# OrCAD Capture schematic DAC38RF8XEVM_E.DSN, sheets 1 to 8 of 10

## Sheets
1 SHEET 02 - DAC: size B; title: DAC; rev: E; note: DAC38RF8xEVM
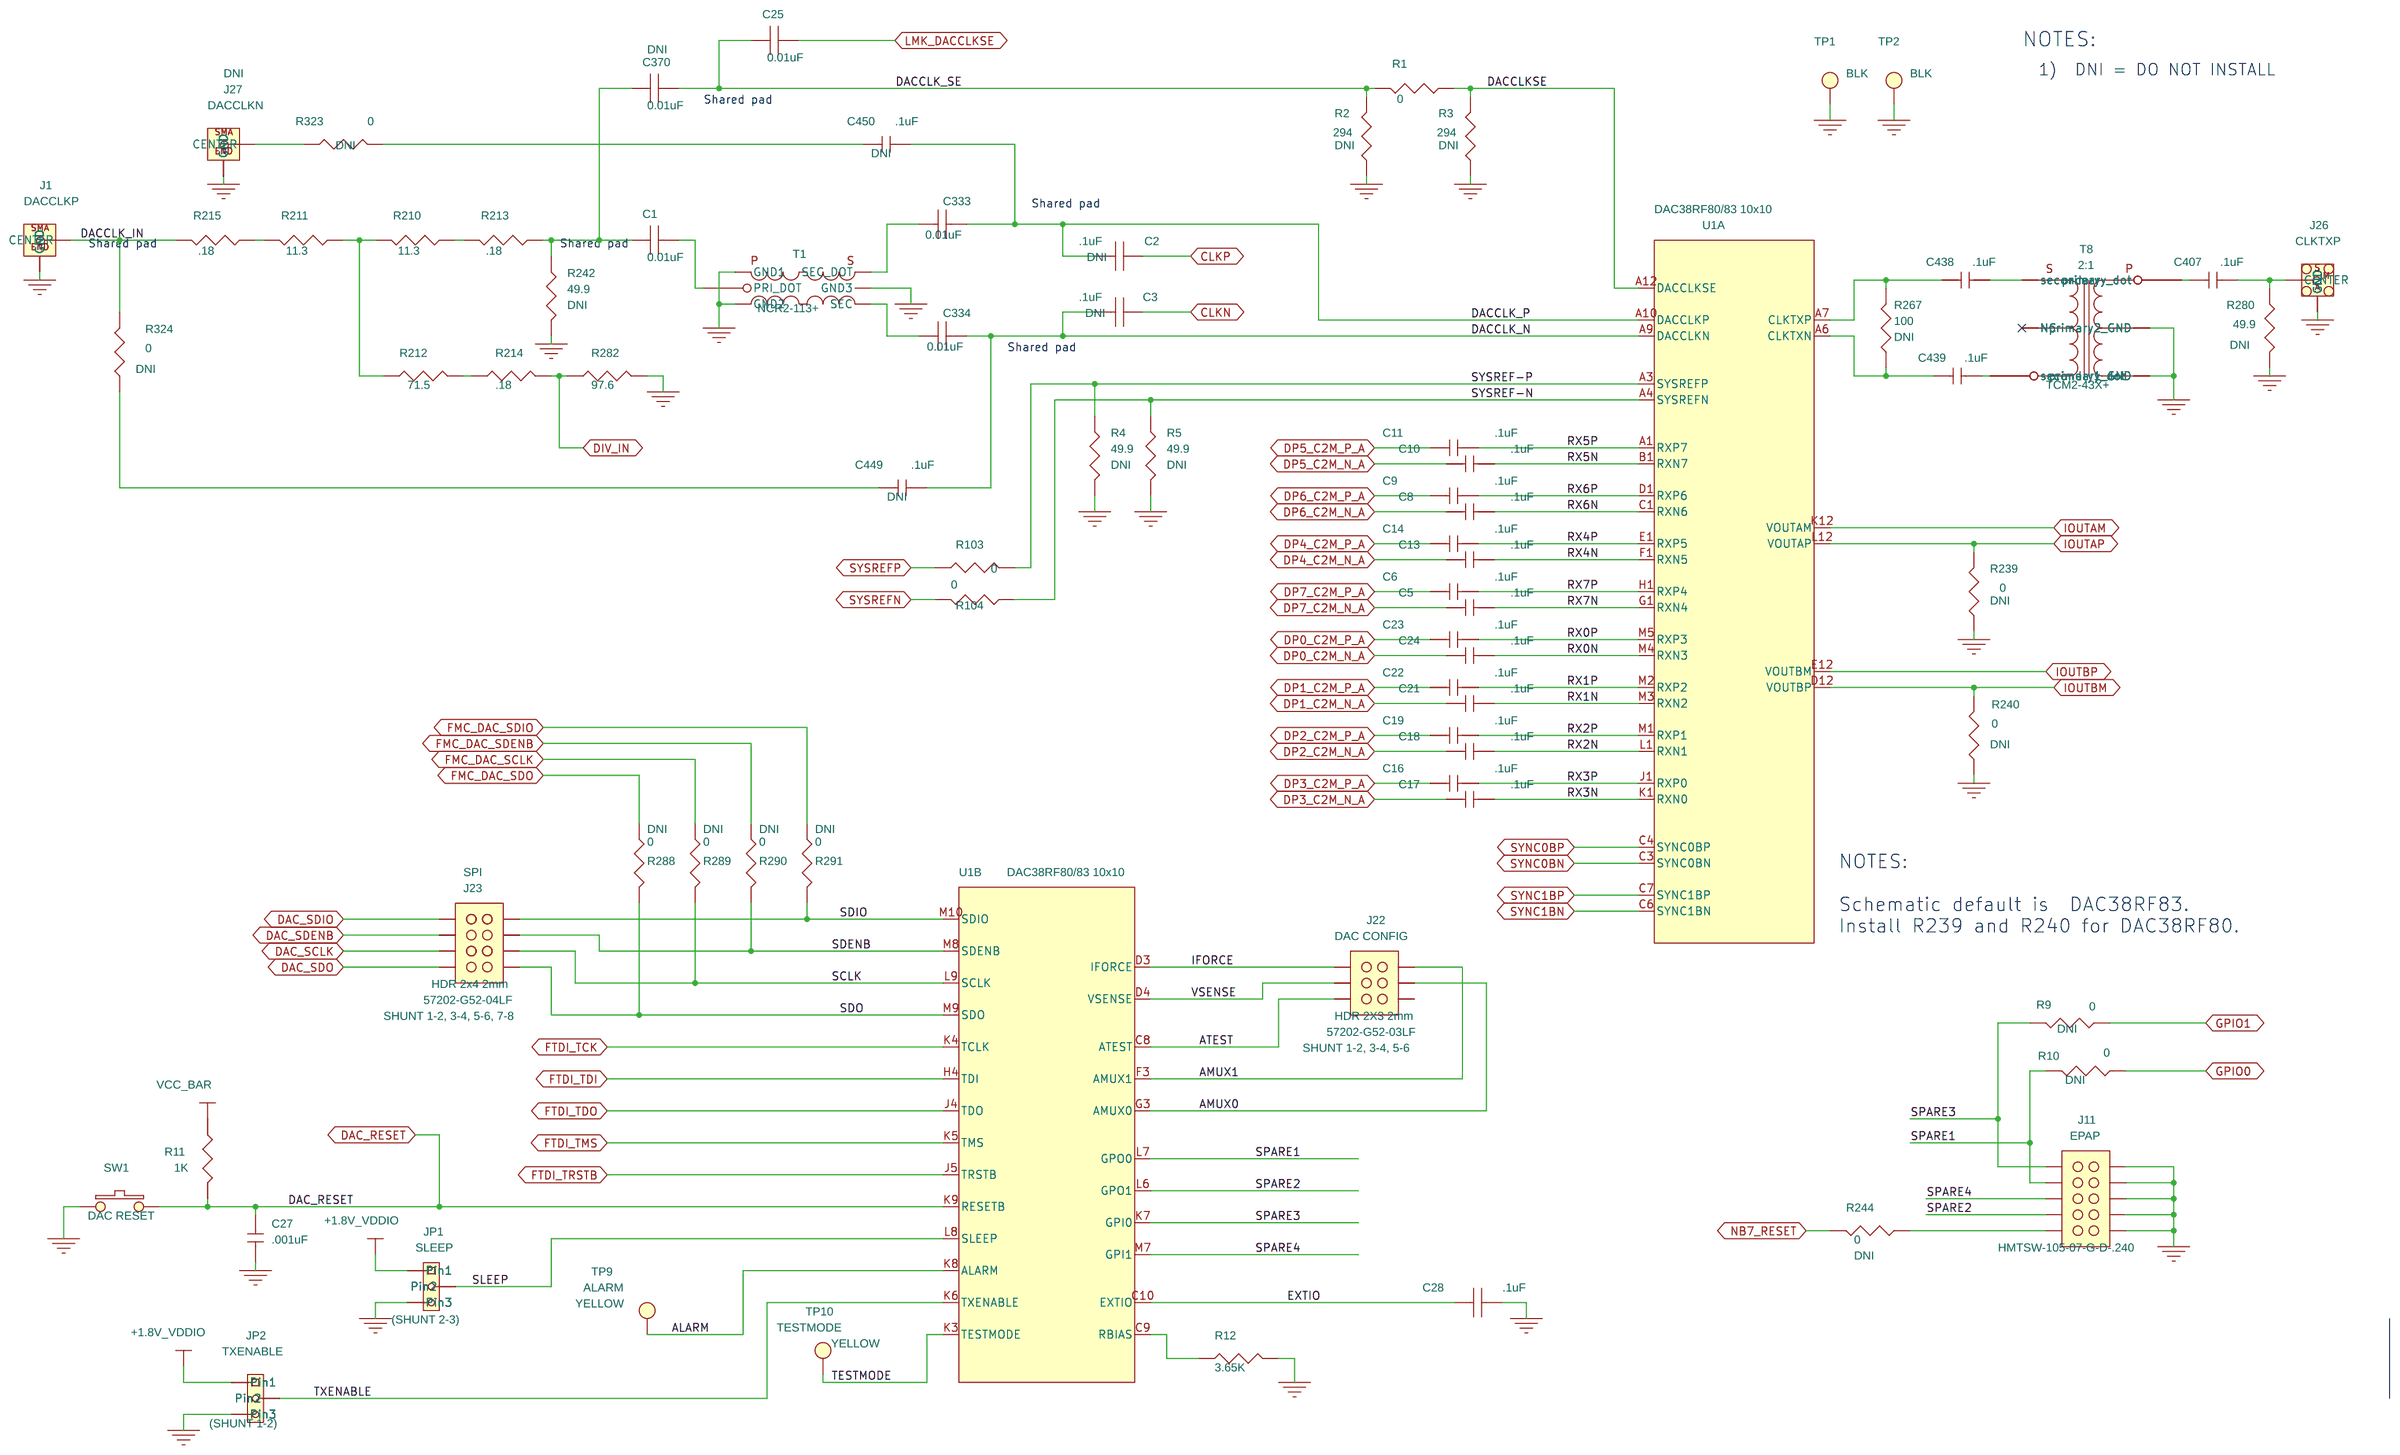
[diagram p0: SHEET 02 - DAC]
2 SHEET 03 - DAC POWER: size B; title: DAC POWER
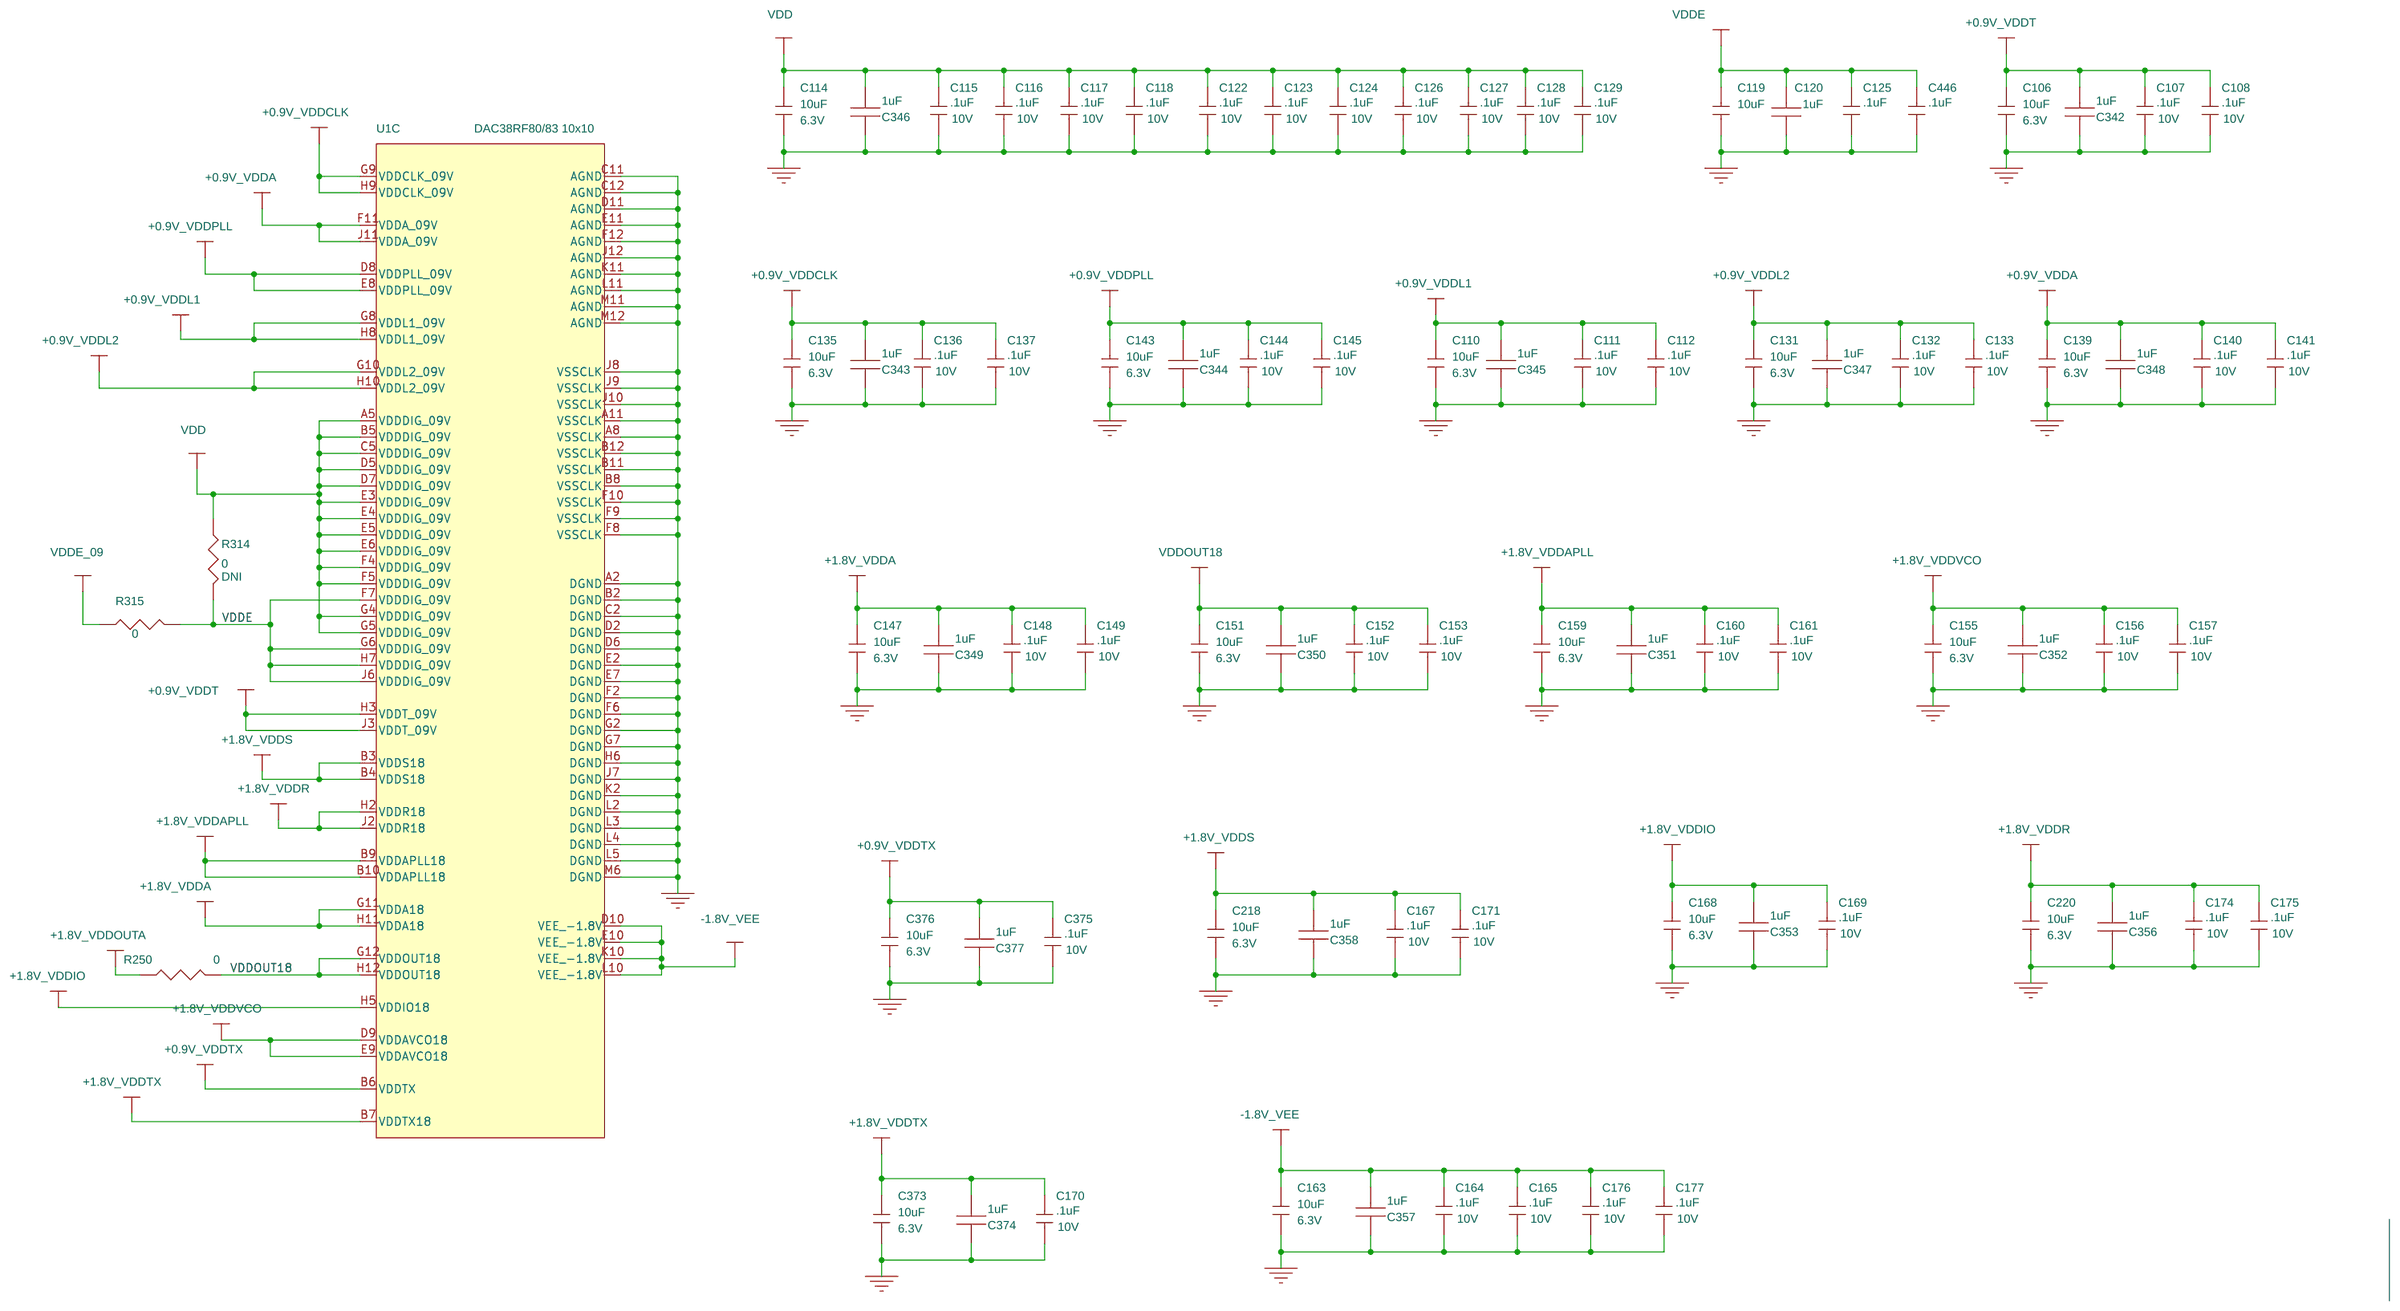
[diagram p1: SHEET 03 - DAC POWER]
3 SHEET 04 - DAC OUTPUTS: size B; title: DAC OUTPUT
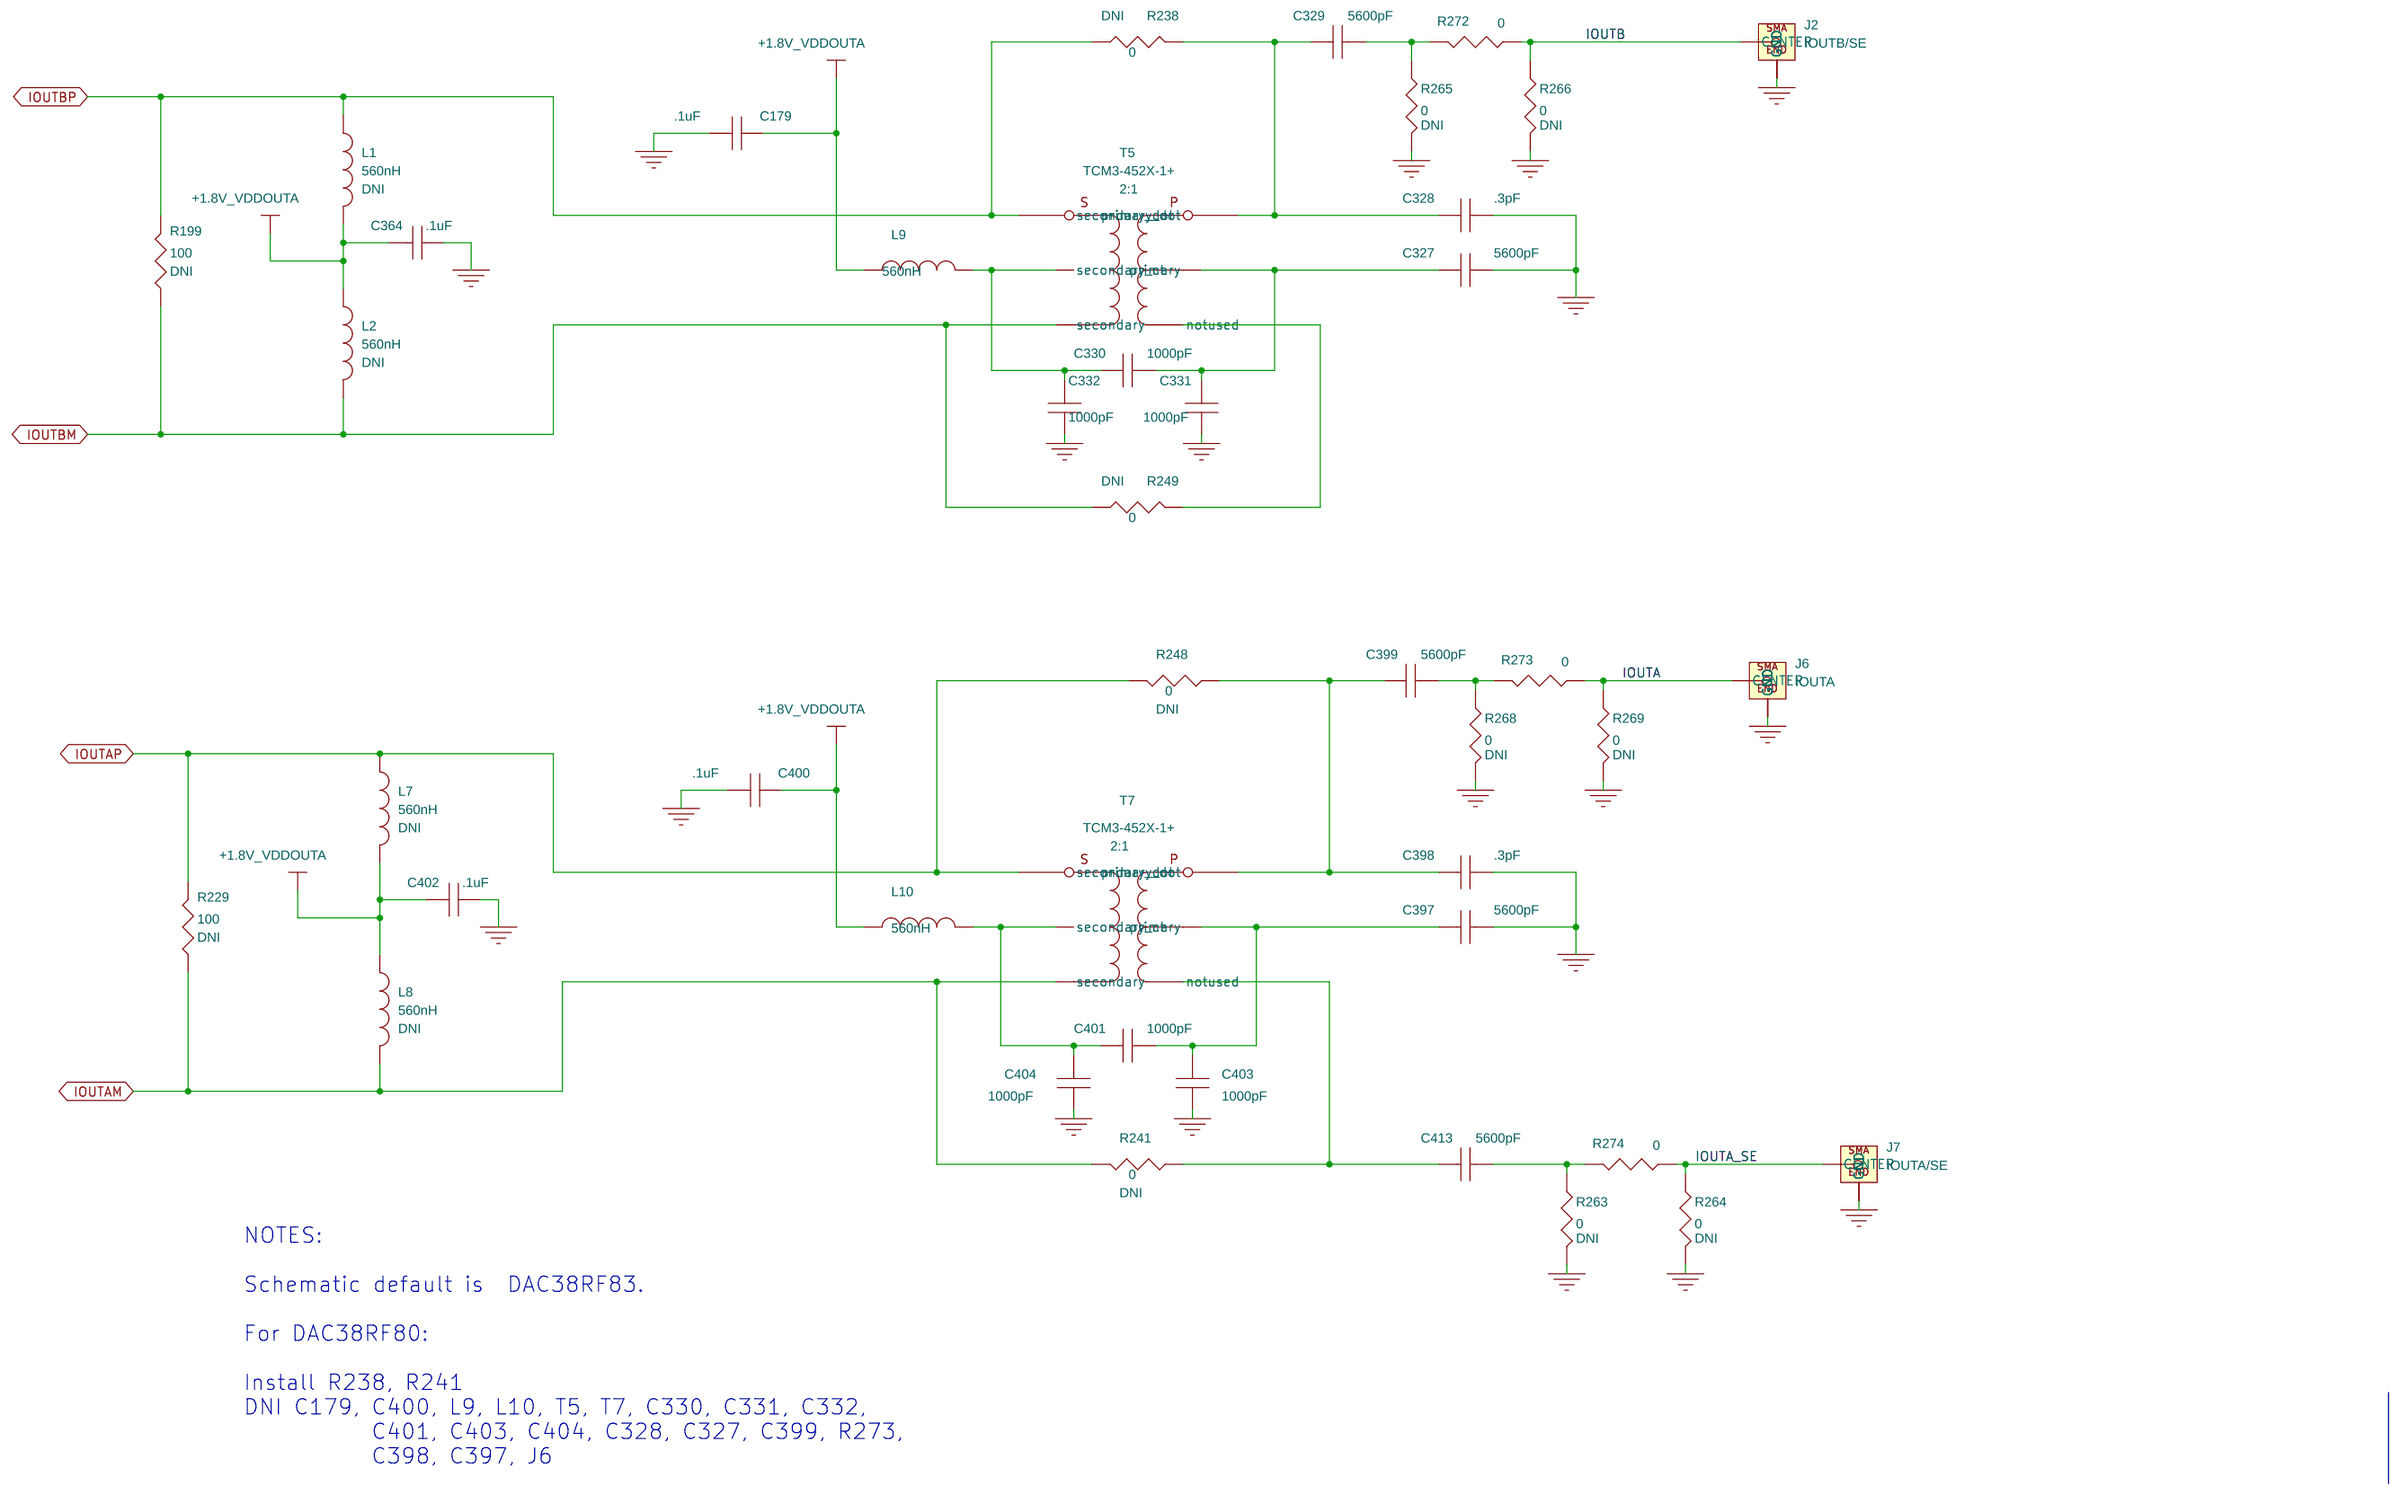
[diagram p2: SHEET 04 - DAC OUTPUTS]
4 SHEET 05 - LMK INPUTS & OUTPUTS: size B; title: LMK
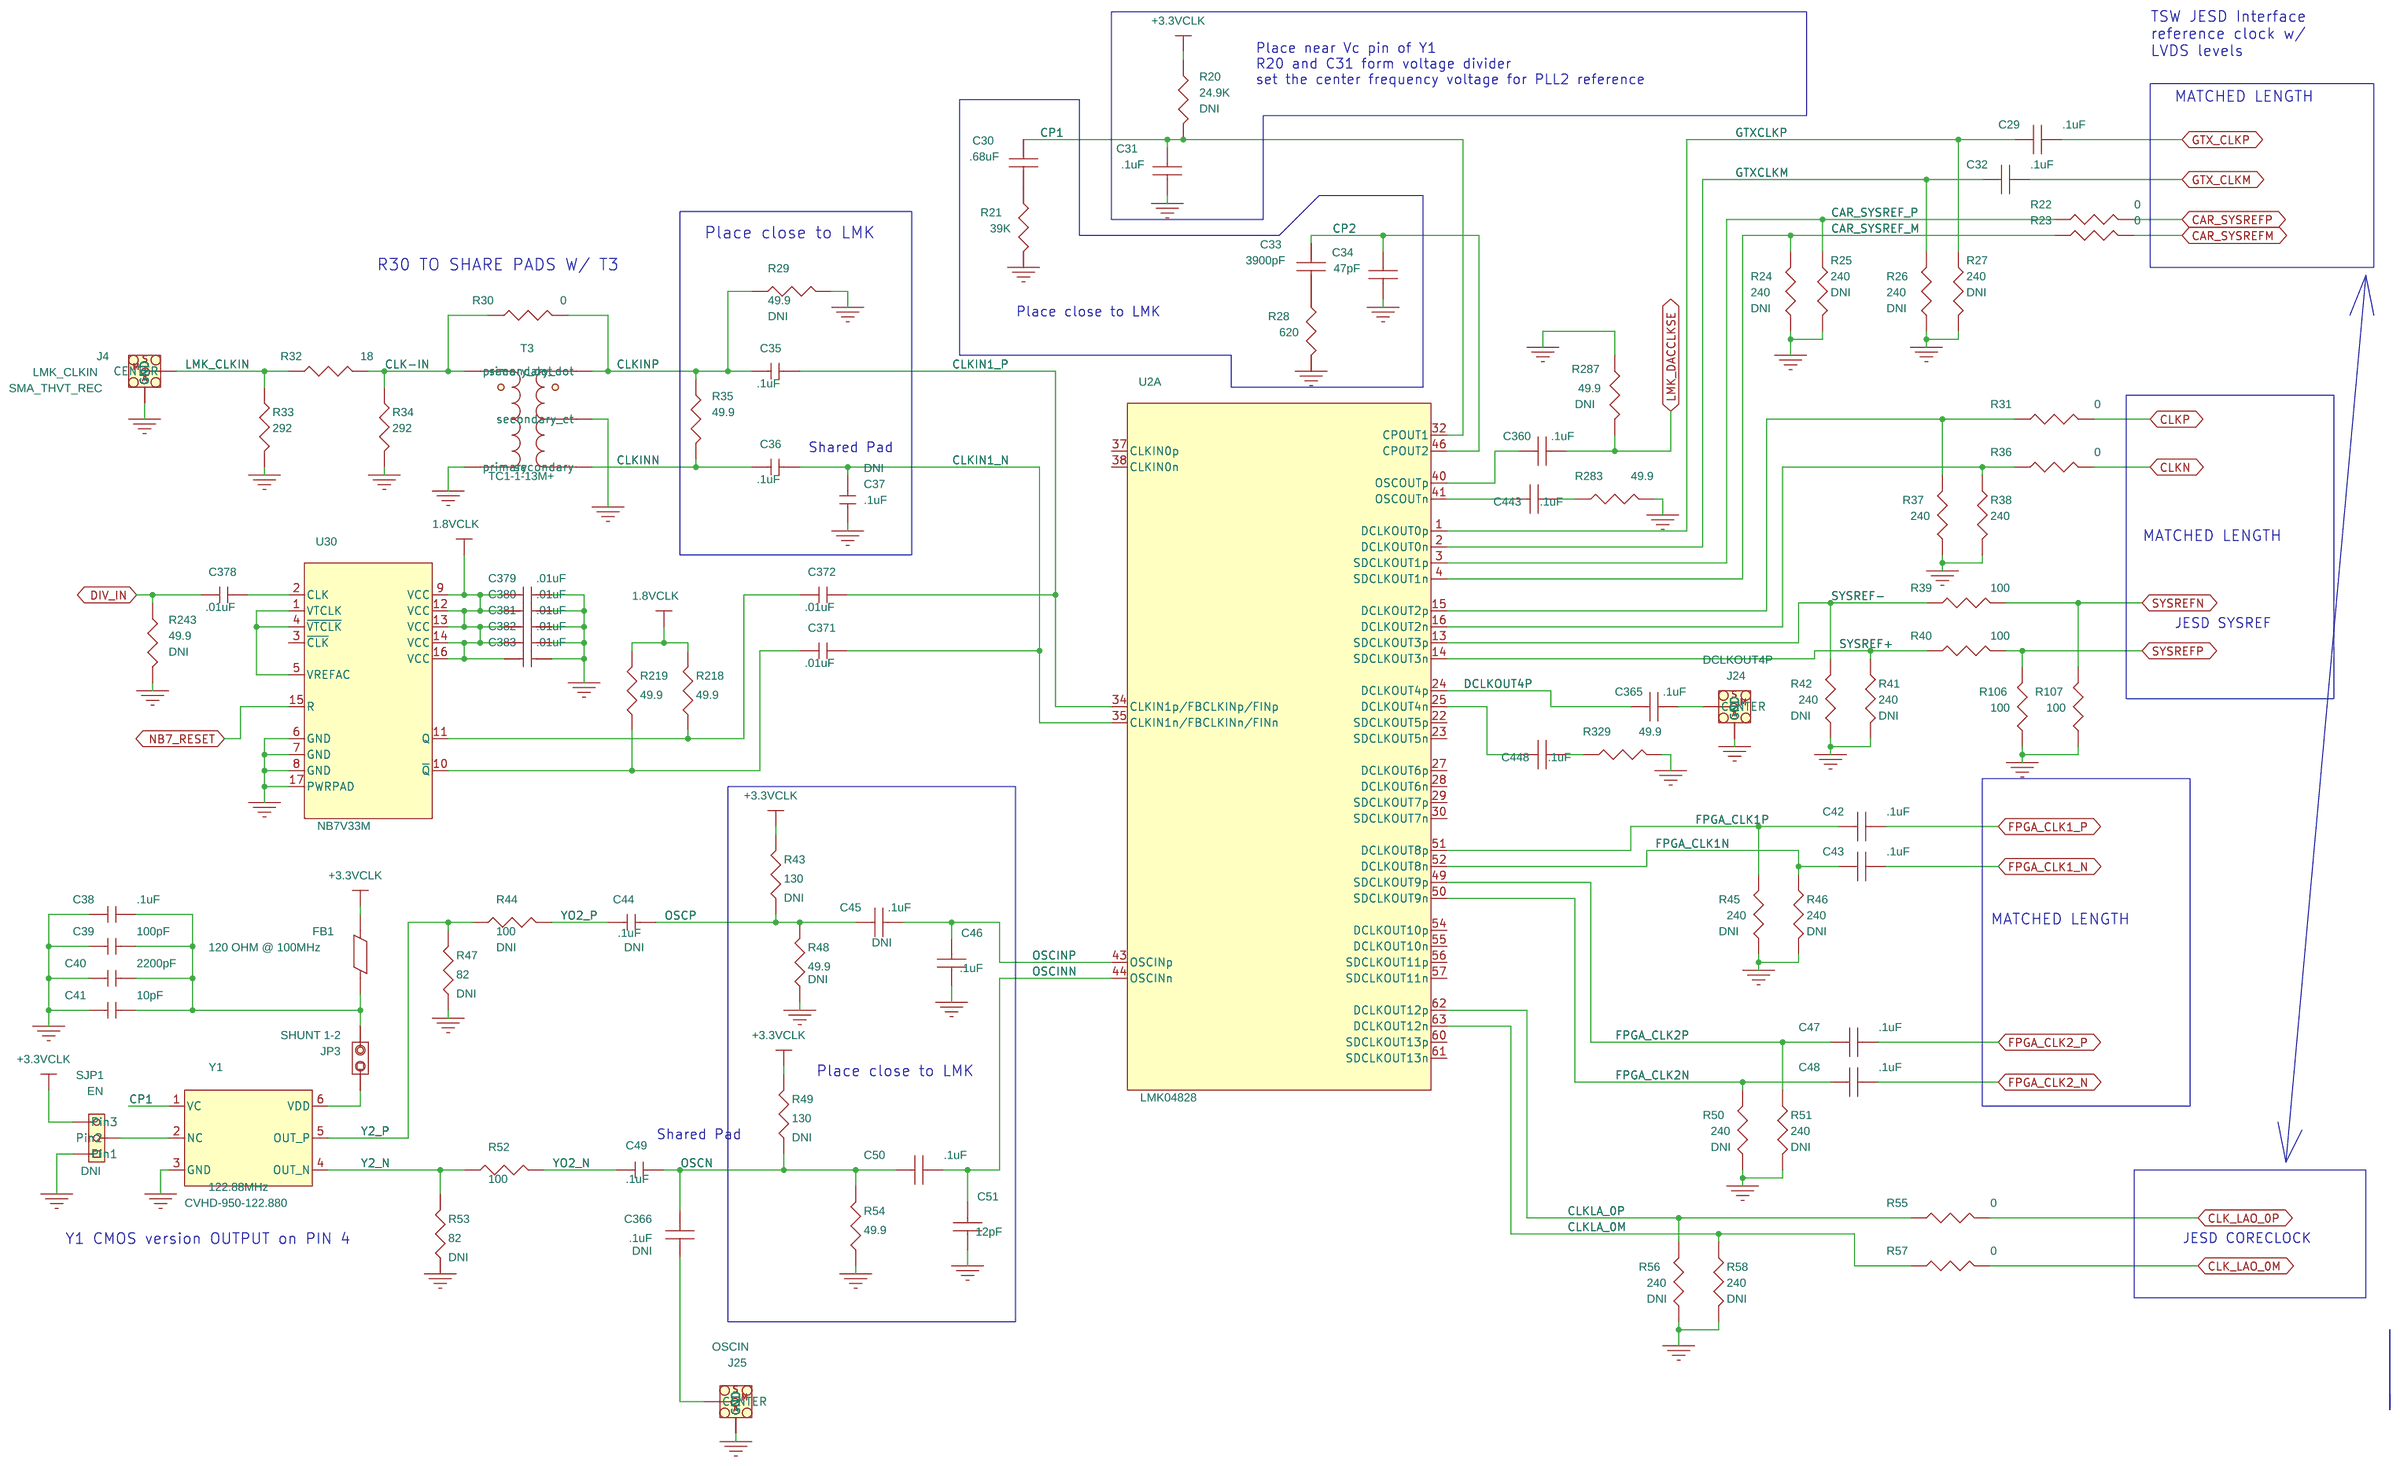
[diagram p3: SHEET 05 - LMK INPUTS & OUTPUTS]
5 SHEET 06 - LMK POWER & CONF: size B; title: LMK
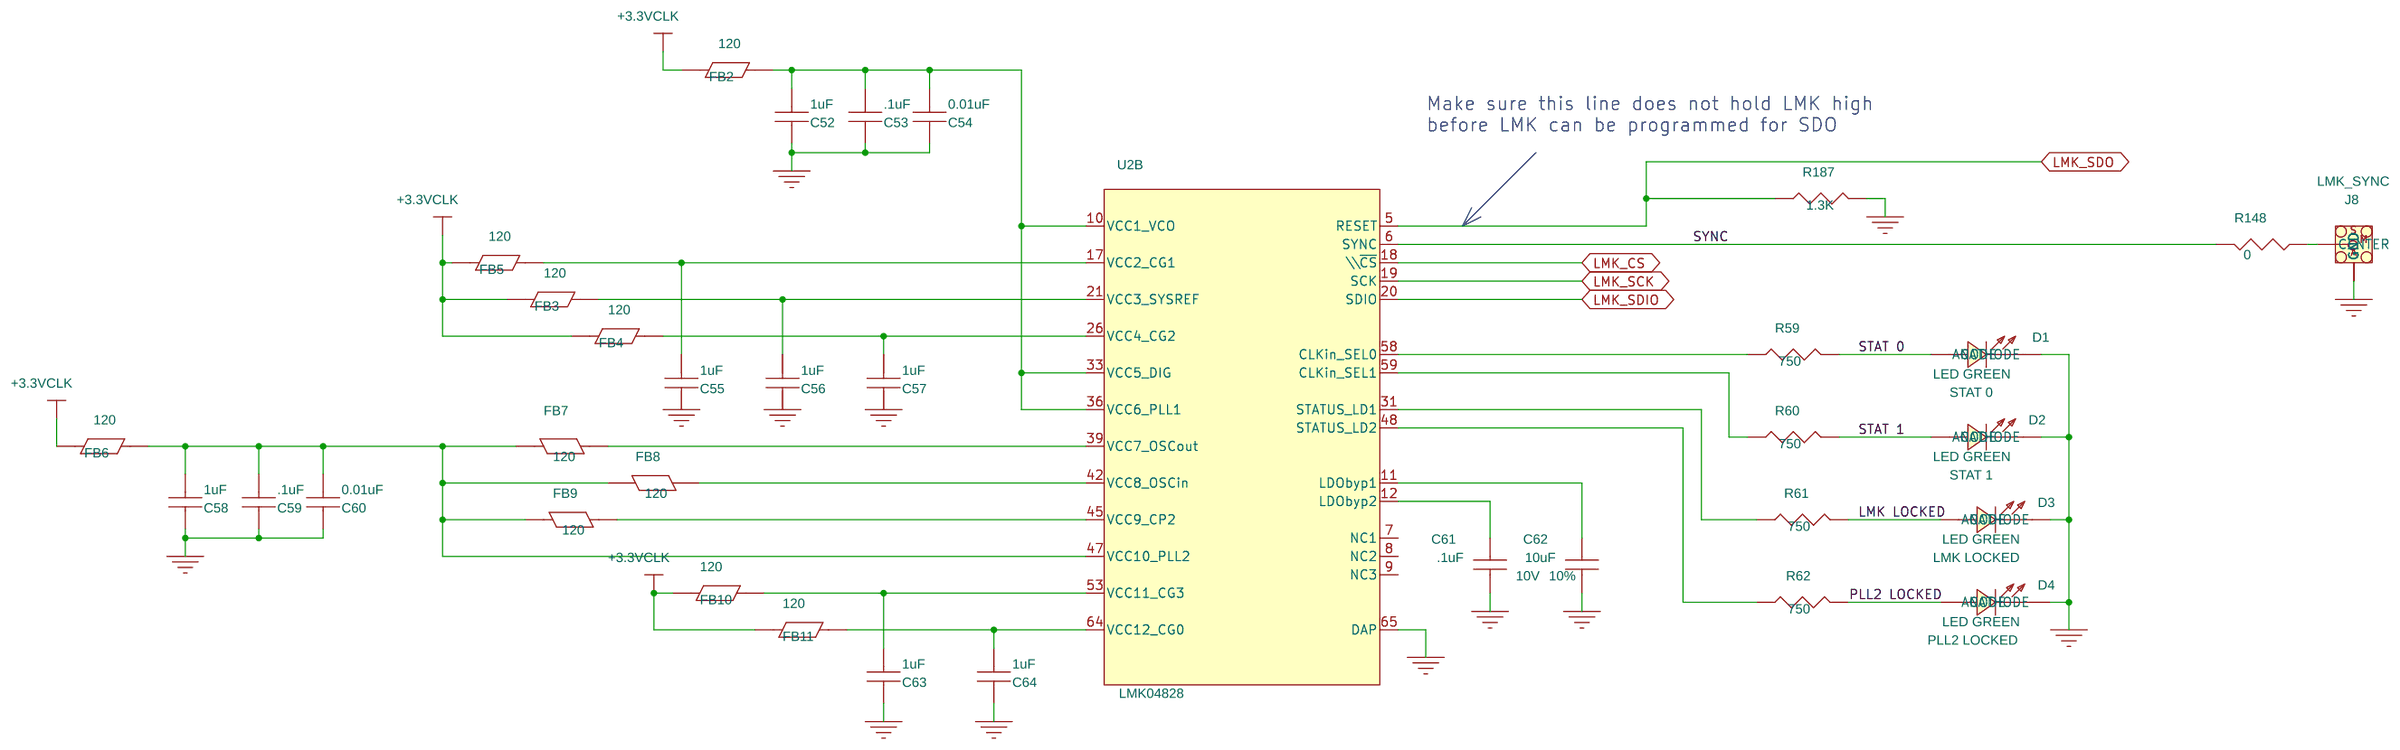
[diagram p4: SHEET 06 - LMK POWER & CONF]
6 SHEET 01 - COVER: title: COVER
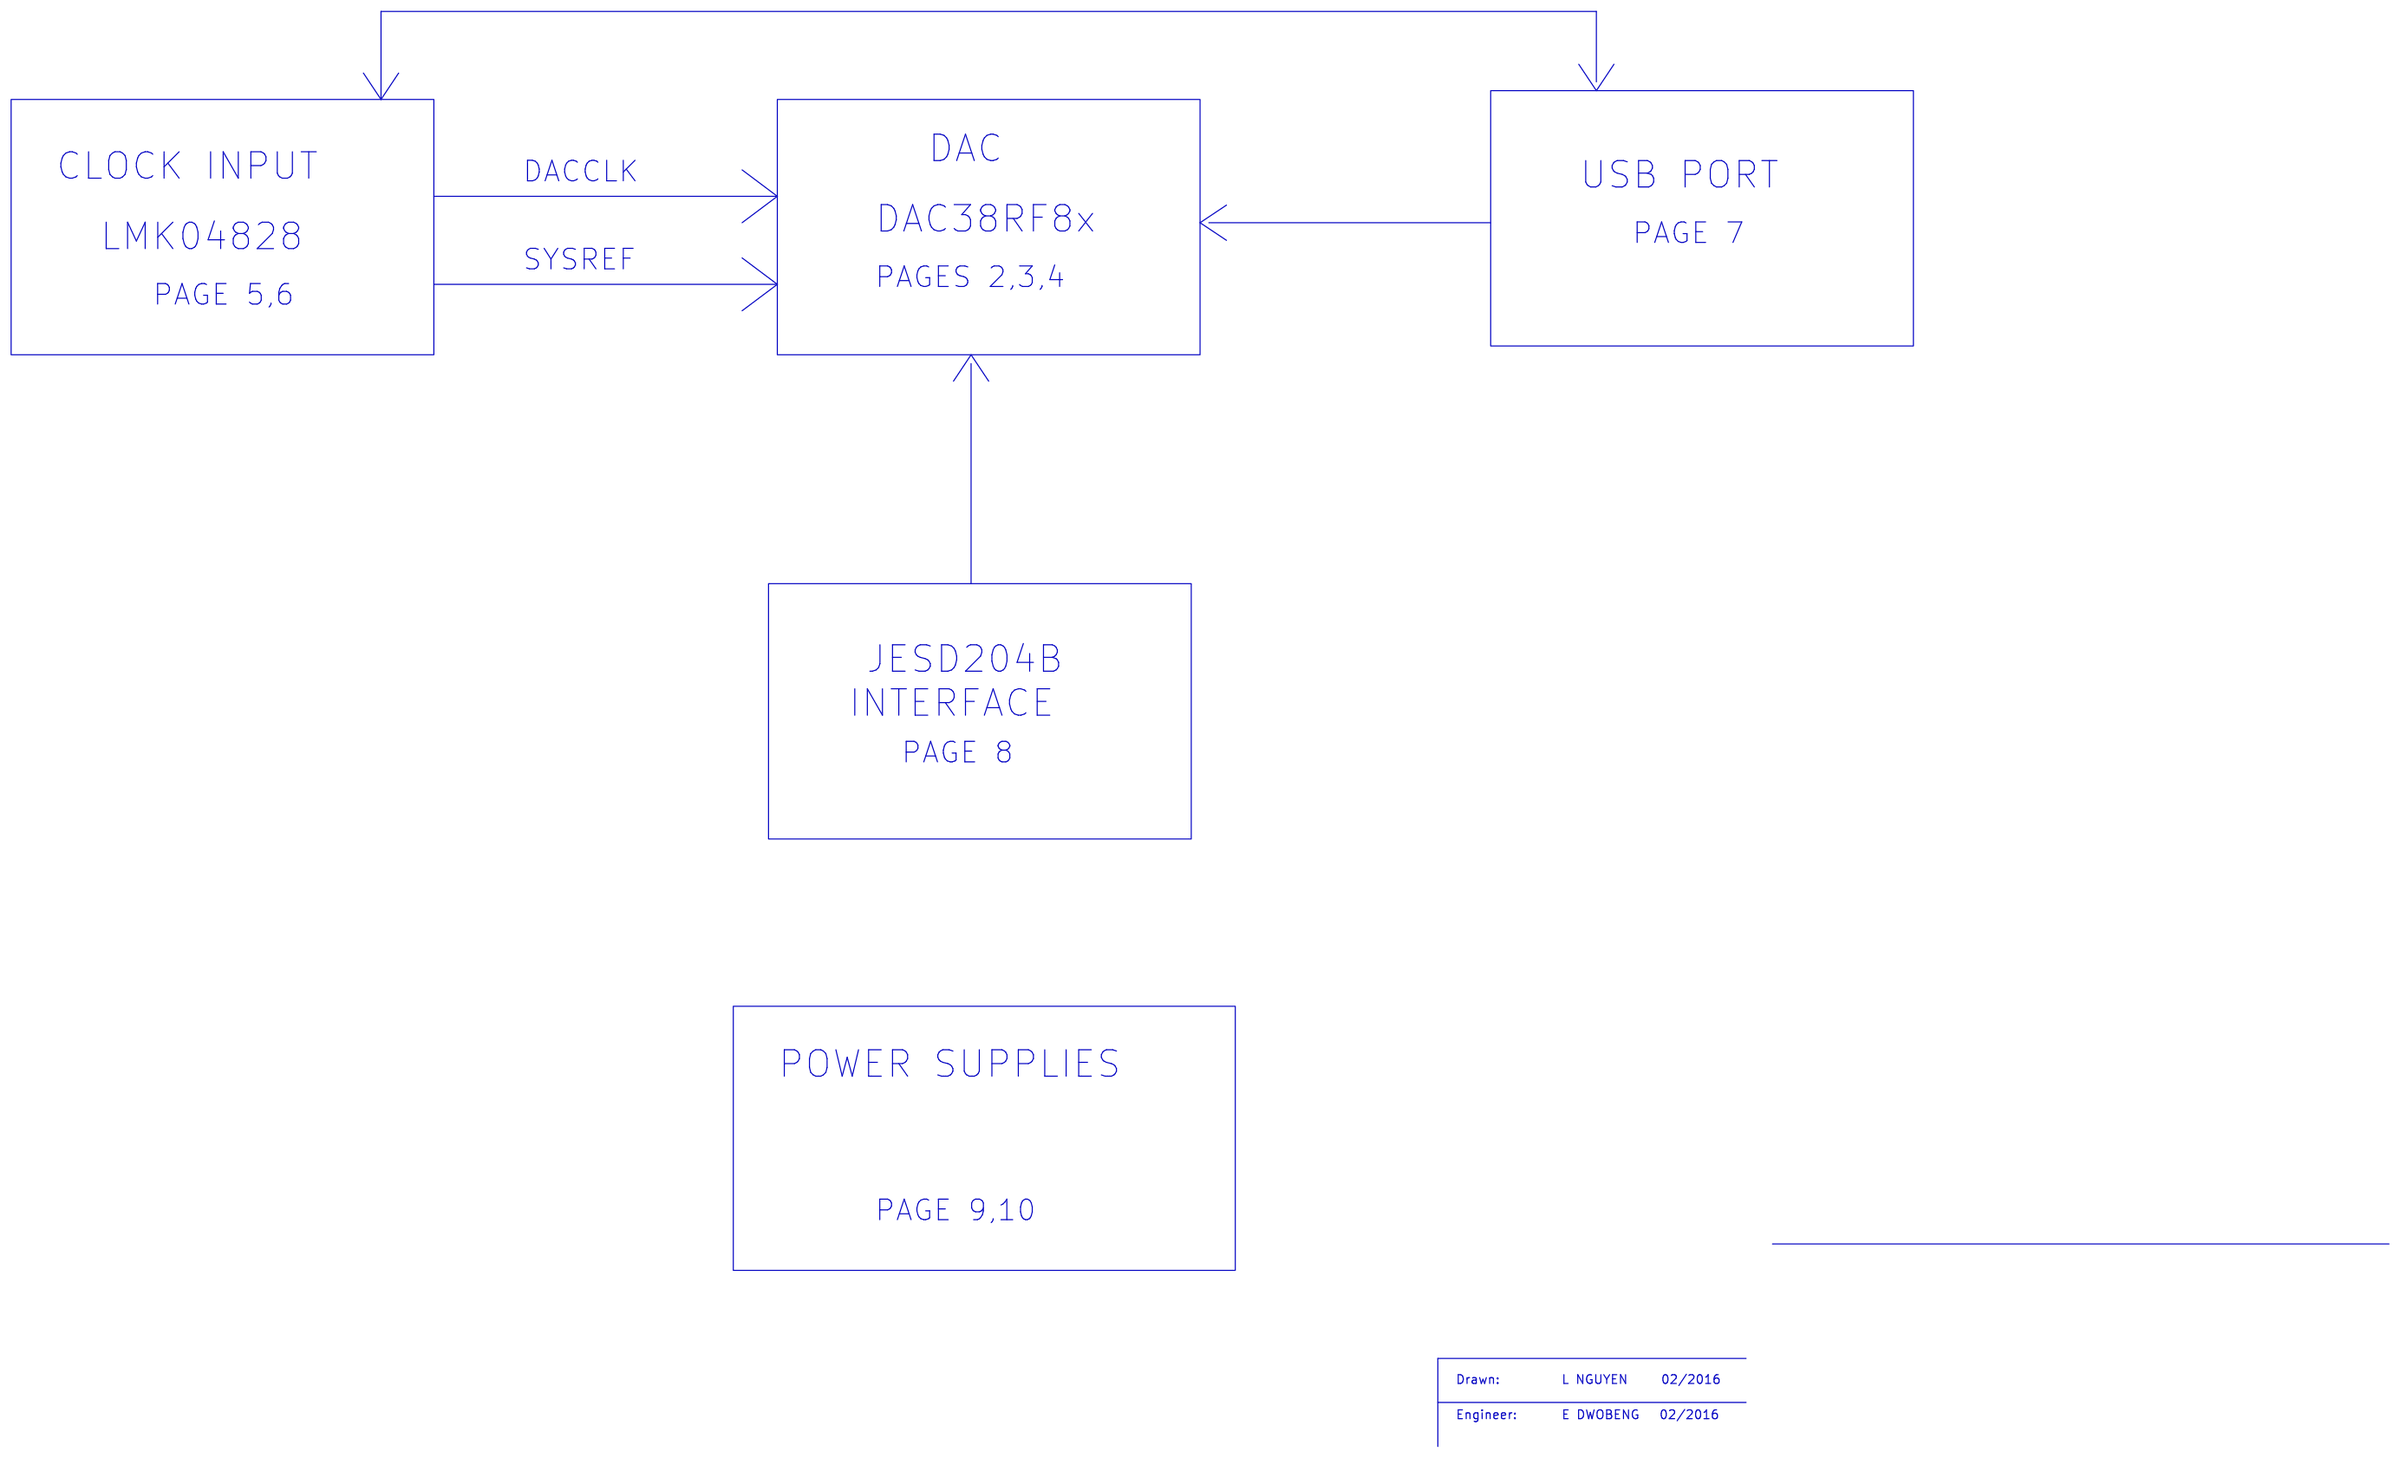
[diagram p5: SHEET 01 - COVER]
7 SHEET 08 - FMC CONN: size B; title: FMC
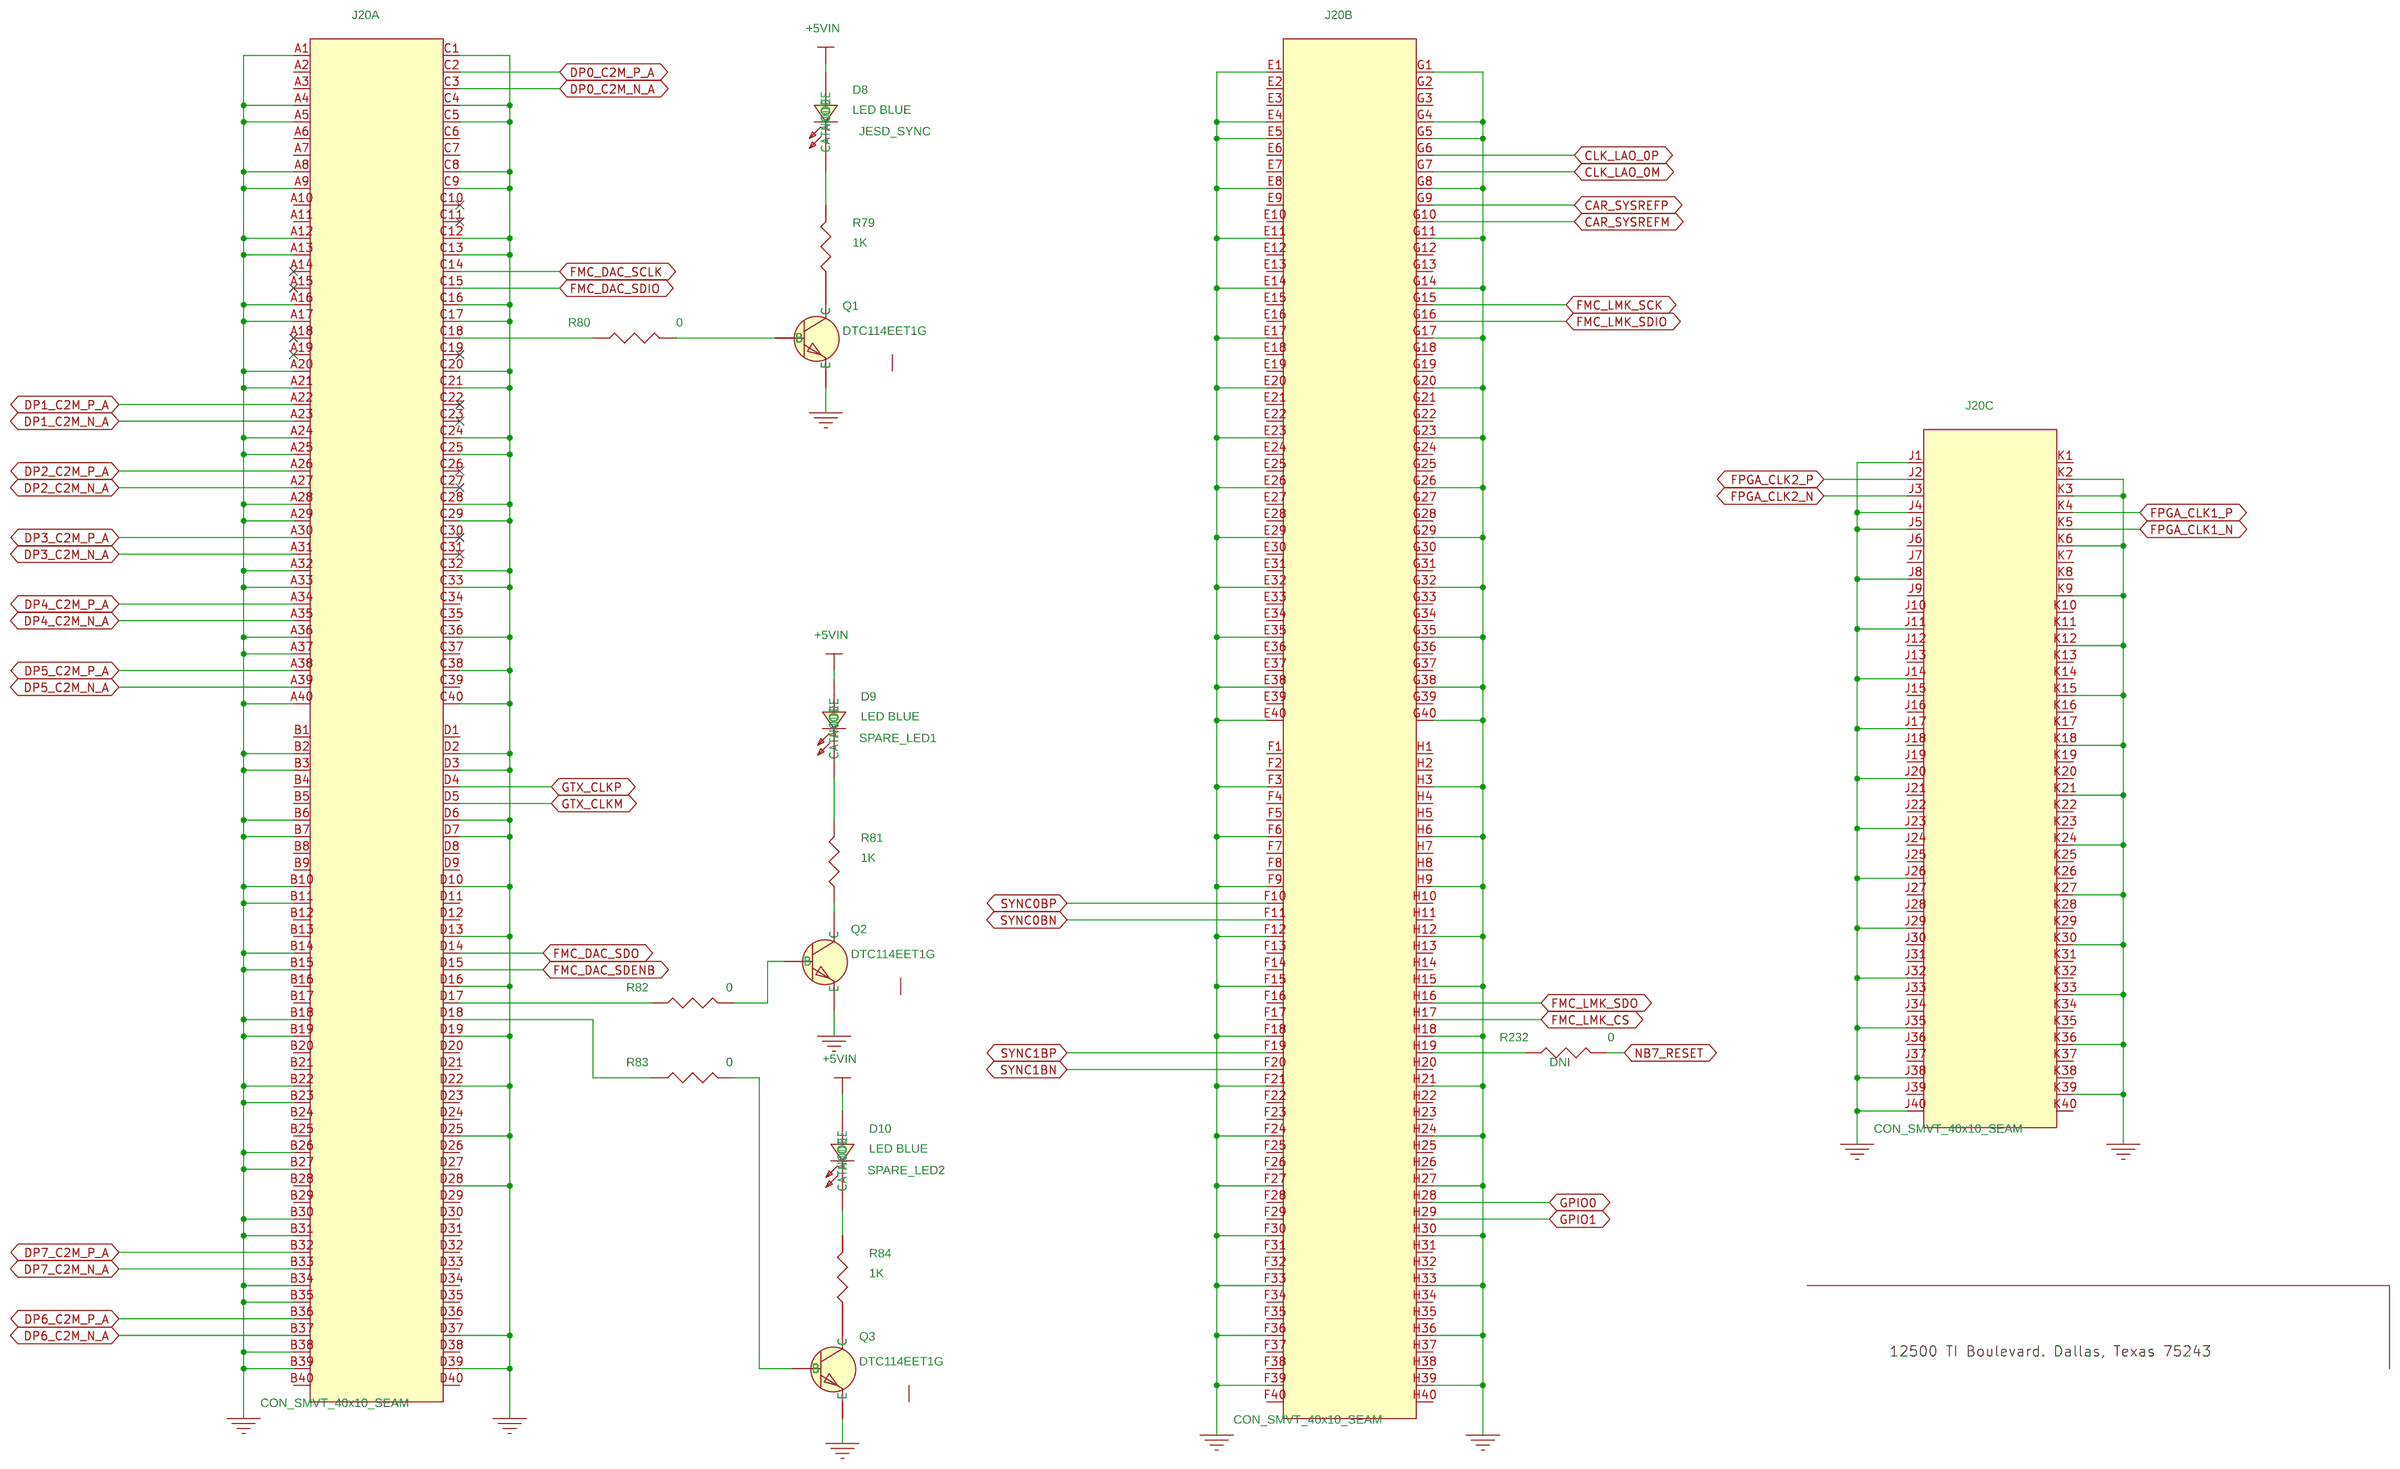
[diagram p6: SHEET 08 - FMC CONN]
8 SHEET 09 - POWER SUPPLIES: size B; title: POWER SUPPLIES +.9V, +1.8V
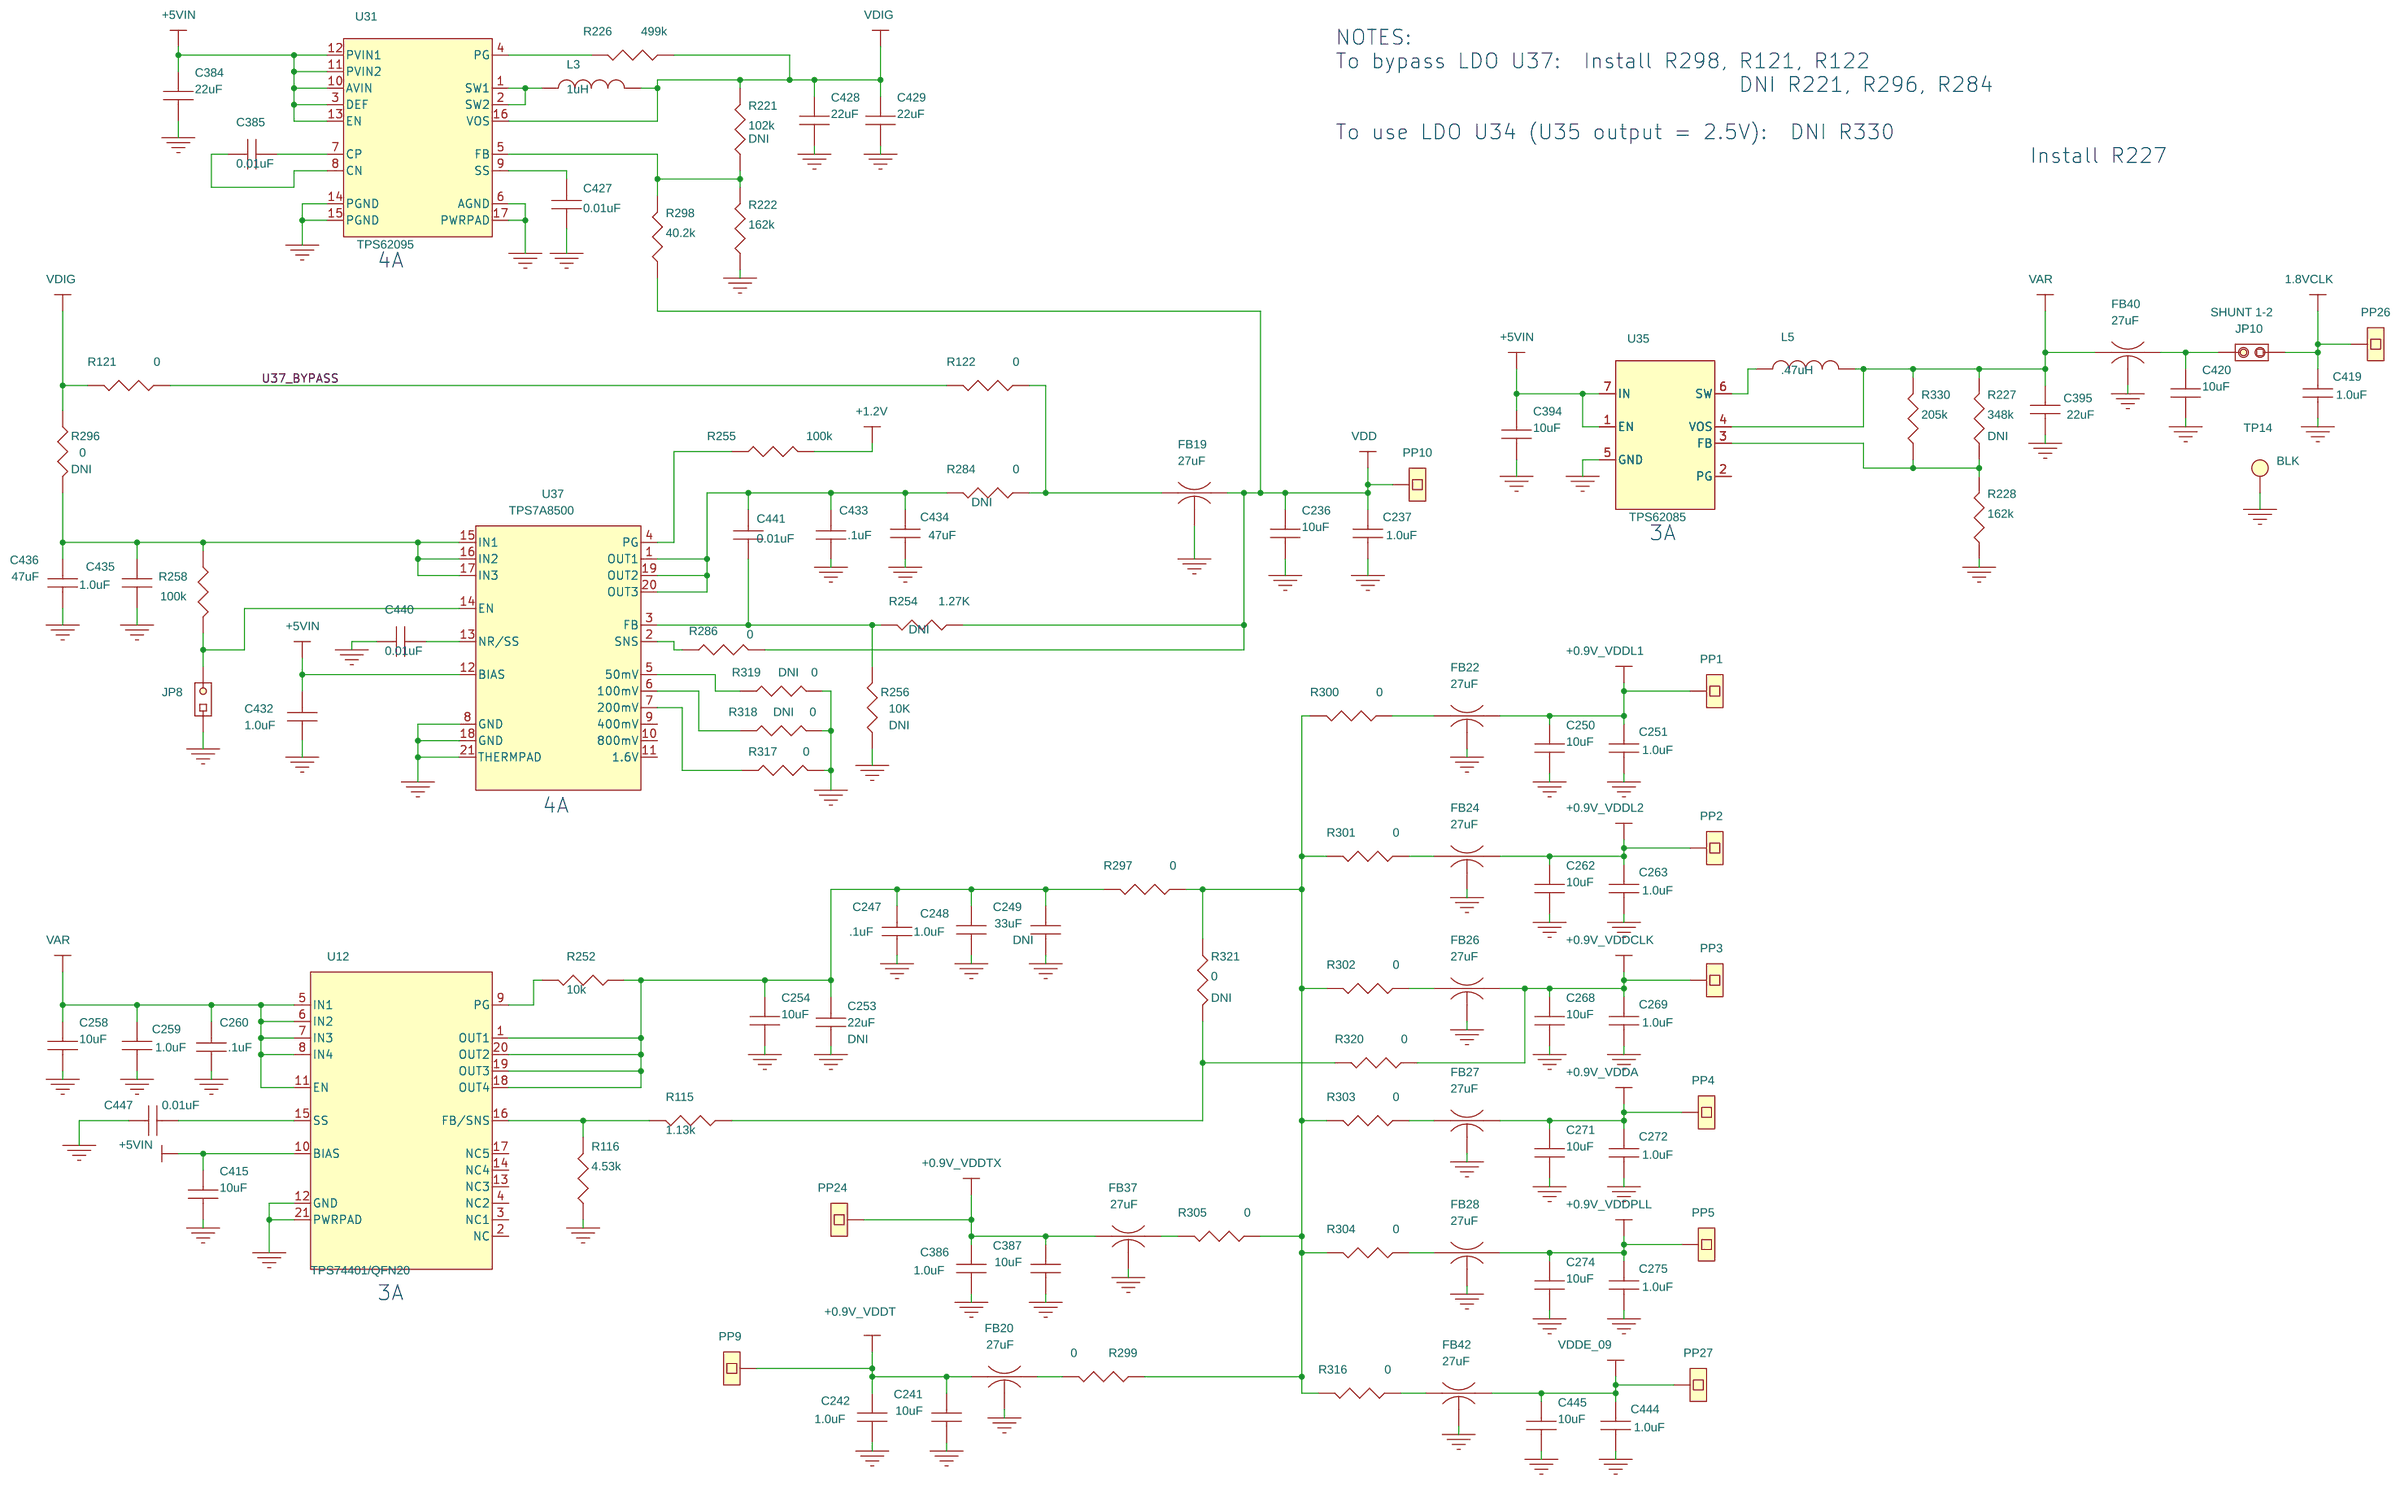
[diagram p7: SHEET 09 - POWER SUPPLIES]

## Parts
sheet SHEET 02 - DAC
C1  0.01uF  [0402]
C2  .1uF  [0201]
C3  .1uF  [0201]
C5  .1uF  [0201]
C6  .1uF  [0201]
C8  .1uF  [0201]
C9  .1uF  [0201]
C10  .1uF  [0201]
C11  .1uF  [0201]
C13  .1uF  [0201]
C14  .1uF  [0201]
C16  .1uF  [0201]
C17  .1uF  [0201]
C18  .1uF  [0201]
C19  .1uF  [0201]
C21  .1uF  [0201]
C22  .1uF  [0201]
C23  .1uF  [0201]
C24  .1uF  [0201]
C25  0.01uF  [0201]
C27  .001uF  [0402]
C28  .1uF  [0201]
C333  0.01uF  [0201]
C334  0.01uF  [0201]
C370  0.01uF  [0402]
C407  .1uF  [0201]
C438  .1uF  [0201]
C439  .1uF  [0201]
C449  .1uF  [0201]
C450  .1uF  [0201]
J1  SMA END LAUNCH  [SMA_SMEL_DUAL_PSF-S01_250x215]
J11  HMTSW-105-07-G-D-.240  [HDR_THVT_2x5_100_M]
J22  HDR 2X3 2mm  [HDR_SMVT_2x3_79_M]
J23  HDR 2x4 2mm  [HDR_SMVT_2x4_79_M]
J26  SMA_THVT_REC  [SMA_THVT_312x312]
J27  SMA END LAUNCH  [SMA_SMEL_DUAL_PSF-S01_250x215]
JP1  Jumper_1x3_100_430L  [HDR_THVT_1x3_100_M]
JP2  Jumper_1x3_100_430L  [HDR_THVT_1x3_100_M]
R1  0  [0201]
R2  294  [0201]
R3  294  [0201]
R4  49.9  [0201]
R5  49.9  [0201]
R9  0  [0402]
R10  0  [0402]
R11  1K  [0402]
R12  3.65K  [0402]
R103  0  [0201]
R104  0  [0201]
R210  11.3  [0402]
R211  11.3  [0402]
R212  71.5  [0402]
R213  .18  [0402]
R214  .18  [0402]
R215  .18  [0402]
R239  0  [0402]
R240  0  [0402]
R242  49.9  [0402]
R244  0  [0402]
R267  100  [0201]
R280  49.9  [0201]
R282  97.6  [0402]
R288  0  [0402]
R289  0  [0402]
R290  0  [0402]
R291  0  [0402]
R323  0  [0402]
R324  0  [0402]
SHN1  SHUNT HEADER
SHN2  SHUNT HEADER
SHN5  SHUNT, JUMPER 2mm
SHN6  SHUNT, JUMPER 2mm
SHN7  SHUNT, JUMPER 2mm
SHN8  SHUNT, JUMPER 2mm
SHN9  SHUNT, JUMPER 2mm
SHN10  SHUNT, JUMPER 2mm
SHN11  SHUNT, JUMPER 2mm
SW1  DAC RESET  [sw_thvt_spst_pts635sl43]
T1  NCR2-113+  [BALUN_6_NCR2]
T8  TCM2-43X+  [TFMR_6_160x150_50]
TP1  BLK  [TP_THVT_060_RND]
TP2  BLK  [TP_THVT_060_RND]
TP9  YELLOW  [TP_THVT_060_RND]
TP10  YELLOW  [TP_THVT_060_RND]
sheet SHEET 03 - DAC POWER
C106  10uF  [0603]
C107  .1uF  [0201]
C108  .1uF  [0201]
C110  10uF  [0603]
C111  .1uF  [0201]
C112  .1uF  [0201]
C114  10uF  [0603]
C115  .1uF  [0201]
C116  .1uF  [0201]
C117  .1uF  [0201]
C118  .1uF  [0201]
C119  10uF  [0603]
C120  1uF  [0201]
C122  .1uF  [0201]
C123  .1uF  [0201]
C124  .1uF  [0201]
C125  .1uF  [0201]
C126  .1uF  [0201]
C127  .1uF  [0201]
C128  .1uF  [0201]
C129  .1uF  [0201]
C131  10uF  [0603]
C132  .1uF  [0201]
C133  .1uF  [0201]
C135  10uF  [0603]
C136  .1uF  [0201]
C137  .1uF  [0201]
C139  10uF  [0603]
C140  .1uF  [0201]
C141  .1uF  [0201]
C143  10uF  [0603]
C144  .1uF  [0201]
C145  .1uF  [0201]
C147  10uF  [0603]
C148  .1uF  [0201]
C149  .1uF  [0201]
C151  10uF  [0603]
C152  .1uF  [0201]
C153  .1uF  [0201]
C155  10uF  [0603]
C156  .1uF  [0201]
C157  .1uF  [0201]
C159  10uF  [0603]
C160  .1uF  [0201]
C161  .1uF  [0201]
C163  10uF  [0603]
C164  .1uF  [0201]
C165  .1uF  [0201]
C167  .1uF  [0201]
C168  10uF  [0603]
C169  .1uF  [0201]
C170  .1uF  [0201]
C171  .1uF  [0201]
C174  .1uF  [0201]
C175  .1uF  [0201]
C176  .1uF  [0201]
C177  .1uF  [0201]
C218  10uF  [0603]
C220  10uF  [0603]
C342  1uF  [0402]
C343  1uF  [0402]
C344  1uF  [0402]
C345  1uF  [0402]
C346  1uF  [0402]
C347  1uF  [0402]
C348  1uF  [0402]
C349  1uF  [0402]
C350  1uF  [0402]
C351  1uF  [0402]
C352  1uF  [0402]
C353  1uF  [0402]
C356  1uF  [0402]
C357  1uF  [0402]
C358  1uF  [0402]
C373  10uF  [0603]
C374  1uF  [0402]
C375  .1uF  [0201]
C376  10uF  [0603]
C377  1uF  [0402]
C446  .1uF  [0201]
R250  0  [0603]
R314  0  [0402]
R315  0  [0805]
U1  DAC38RF80/83 10x10  [BGA_144_10MMx10MM_0P80MM]  (sections A,B,C)
sheet SHEET 04 - DAC OUTPUTS
C179  .1uF  [0402]
C327  5600pF  [0402]
C328  .3pF  [0402]
C329  5600pF  [0402]
C330  1000pF  [0402]
C331  1000pF  [0402]
C332  1000pF  [0402]
C364  .1uF  [0402]
C397  5600pF  [0402]
C398  .3pF  [0402]
C399  5600pF  [0402]
C400  .1uF  [0402]
C401  1000pF  [0402]
C402  .1uF  [0402]
C403  1000pF  [0402]
C404  1000pF  [0402]
C413  5600pF  [0402]
J2  SMA END LAUNCH  [SMA_SMEL_DUAL_PSF-S01_250x215]
J6  SMA END LAUNCH  [SMA_SMEL_DUAL_PSF-S01_250x215]
J7  SMA END LAUNCH  [SMA_SMEL_DUAL_PSF-S01_250x215]
L1  560nH  [0402]
L2  560nH  [0402]
L7  560nH  [0402]
L8  560nH  [0402]
L9  560nH  [0402]
L10  560nH  [0402]
R199  100  [0402]
R229  100  [0402]
R238  0  [0603]
R241  0  [0603]
R248  0  [0603]
R249  0  [0603]
R263  0  [0402]
R264  0  [0402]
R265  0  [0402]
R266  0  [0402]
R268  0  [0402]
R269  0  [0402]
R272  0  [0402]
R273  0  [0402]
R274  0  [0402]
T5  TCM3-452X-1+  [TFMR_6_160x150_50]
T7  TCM3-452X-1+  [TFMR_6_160x150_50]
sheet SHEET 05 - LMK INPUTS & OUTPUTS
C29  .1uF  [0201]
C30  .68uF  [0402]
C31  .1uF  [0201]
C32  .1uF  [0201]
C33  3900pF  [0201]
C34  47pF  [0201]
C35  .1uF  [0201]
C36  .1uF  [0201]
C37  .1uF  [0201]
C38  .1uF  [0201]
C39  100pF  [0402]
C40  2200pF  [0402]
C41  10pF  [0402]
C42  .1uF  [0201]
C43  .1uF  [0201]
C44  .1uF  [0201]
C45  .1uF  [0201]
C46  .1uF  [0201]
C47  .1uF  [0201]
C48  .1uF  [0201]
C49  .1uF  [0201]
C50  .1uF  [0201]
C51  12pF  [0201]
C360  .1uF  [0201]
C365  .1uF  [0201]
C366  .1uF  [0201]
C371  .01uF  [0201]
C372  .01uF  [0201]
C378  .01uF  [0201]
C379  .01uF  [0201]
C380  .01uF  [0201]
C381  .01uF  [0201]
C382  .01uF  [0201]
C383  .01uF  [0201]
C443  .1uF  [0201]
C448  .1uF  [0201]
FB1  120 OHM @ 100MHz  [1206]
J4  SMA_THVT_REC  [SMA_THVT_312x312]
J24  SMA_THVT_REC  [SMA_THVT_312x312]
J25  SMA_THVT_REC  [SMA_THVT_312x312]
JP3  HEADER_1x2_100_430L  [HDR_THVT_1x2_100_M]
R20  24.9K  [0201]
R21  39K  [0201]
R22  0  [0201]
R23  0  [0201]
R24  240  [0201]
R25  240  [0201]
R26  240  [0201]
R27  240  [0201]
R28  620  [0201]
R29  49.9  [0201]
R30  0  [0603]
R31  0  [0201]
R32  18  [0402]
R33  292  [0402]
R34  292  [0402]
R35  49.9  [0402]
R36  0  [0201]
R37  240  [0201]
R38  240  [0201]
R39  100  [0201]
R40  100  [0201]
R41  240  [0201]
R42  240  [0201]
R43  130  [0201]
R44  100  [0201]
R45  240  [0201]
R46  240  [0201]
R47  82  [0201]
R48  49.9  [0201]
R49  130  [0201]
R50  240  [0201]
R51  240  [0201]
R52  100  [0201]
R53  82  [0201]
R54  49.9  [0201]
R55  0  [0201]
R56  240  [0201]
R57  0  [0201]
R58  240  [0201]
R106  100  [0201]
R107  100  [0201]
R218  49.9  [0201]
R219  49.9  [0201]
R243  49.9  [0201]
R283  49.9  [0201]
R287  49.9  [0201]
R329  49.9  [0201]
SHN17  SHUNT HEADER
SJP1  SOLDER JUMPER, 0402  [SMD_JUMPER_L_0402]
T3  TC1-1-13M+  [TFMR_5_150x150_50]
U2  LMK04828  [QFN_64_360X360_0P50MM_PWRPAD]  (sections A,B)
U30  NB7V33M  [qfn_16_124x124_pwrpad]
Y1  122.88MHz  [VCXO_6_CUSTOM]
sheet SHEET 06 - LMK POWER & CONF
C52  1uF  [0402]
C53  .1uF  [0402]
C54  0.01uF  [0402]
C55  1uF  [0603]
C56  1uF  [0603]
C57  1uF  [0603]
C58  1uF  [0402]
C59  .1uF  [0402]
C60  0.01uF  [0402]
C61  .1uF  [0402]
C62  10uF  [0603]
C63  1uF  [0603]
C64  1uF  [0603]
D1  LED GREEN  [LED_1206]
D2  LED GREEN  [LED_1206]
D3  LED GREEN  [LED_1206]
D4  LED GREEN  [LED_1206]
FB2  120  [0603]
FB3  120  [0603]
FB4  120  [0603]
FB5  120  [0603]
FB6  120  [0603]
FB7  120  [0603]
FB8  120  [0603]
FB9  120  [0603]
FB10  120  [0603]
FB11  120  [0603]
J8  SMA_THVT_REC  [SMA_THVT_312x312]
R59  750  [0603]
R60  750  [0603]
R61  750  [0603]
R62  750  [0603]
R148  0  [0402]
R187  1.3K  [0402]
sheet SHEET 08 - FMC CONN
D8  LED BLUE  [LED_0805]
D9  LED BLUE  [LED_0805]
D10  LED BLUE  [LED_0805]
J20  CON_SMVT_40x10_SEAM  [CON_SMVT_40X10_SEAM_MTG]  (sections A,B,C)
Q1  DTC114EET1G  [SOT_416_3_63x31]
Q2  DTC114EET1G  [SOT_416_3_63x31]
Q3  DTC114EET1G  [SOT_416_3_63x31]
R79  1K  [0402]
R80  0  [0402]
R81  1K  [0402]
R82  0  [0402]
R83  0  [0402]
R84  1K  [0402]
R232  0  [0402]
sheet SHEET 09 - POWER SUPPLIES
C236  10uF  [0805]
C237  1.0uF  [0603]
C241  10uF  [0805]
C242  1.0uF  [0603]
C247  .1uF  [0402]
C248  1.0uF  [0603]
C249  33uF  [1812]
C250  10uF  [0805]
C251  1.0uF  [0603]
C253  22uF  [1206]
C254  10uF  [0805]
C258  10uF  [0805]
C259  1.0uF  [0603]
C260  .1uF  [0402]
C262  10uF  [0805]
C263  1.0uF  [0603]
C268  10uF  [0805]
C269  1.0uF  [0603]
C271  10uF  [0805]
C272  1.0uF  [0603]
C274  10uF  [0805]
C275  1.0uF  [0603]
C384  22uF  [1206]
C385  0.01uF  [0402]
C386  1.0uF  [0603]
C387  10uF  [0805]
C394  10uF  [0805]
C395  22uF  [1206]
C415  10uF  [0805]
C419  1.0uF  [0603]
C420  10uF  [0805]
C427  0.01uF  [0402]
C428  22uF  [1206]
C429  22uF  [1206]
C432  1.0uF  [0603]
C433  .1uF  [0402]
C434  47uF  [0805]
C435  1.0uF  [0603]
C436  47uF  [0805]
C440  0.01uF  [0402]
C441  0.01uF  [0402]
C444  1.0uF  [0603]
C445  10uF  [0805]
C447  0.01uF  [0402]
FB19  27uF  [1206_BEAD_NFM31P]
FB20  27uF  [1206_BEAD_NFM31P]
FB22  27uF  [1206_BEAD_NFM31P]
FB24  27uF  [1206_BEAD_NFM31P]
FB26  27uF  [1206_BEAD_NFM31P]
FB27  27uF  [1206_BEAD_NFM31P]
FB28  27uF  [1206_BEAD_NFM31P]
FB37  27uF  [1206_BEAD_NFM31P]
FB40  27uF  [1206_BEAD_NFM31P]
FB42  27uF  [1206_BEAD_NFM31P]
JP8  HEADER_1x2_100_430L  [HDR_THVT_1x2_100_M]
JP10  HEADER_1x2_100_430L  [HDR_THVT_1x2_100_M]
L3  1uH  [IND_SM_XFL4015]
L5  .47uH  [IND_SM_XFL4015]
PP1  PROBE POINT  [PROBE_POINT_22PAD]
PP2  PROBE POINT  [PROBE_POINT_22PAD]
PP3  PROBE POINT  [PROBE_POINT_22PAD]
PP4  PROBE POINT  [PROBE_POINT_22PAD]
PP5  PROBE POINT  [PROBE_POINT_22PAD]
PP9  PROBE POINT  [PROBE_POINT_22PAD]
PP10  PROBE POINT  [PROBE_POINT_22PAD]
PP24  PROBE POINT  [PROBE_POINT_22PAD]
PP26  PROBE POINT  [PROBE_POINT_22PAD]
PP27  PROBE POINT  [PROBE_POINT_22PAD]
R115  1.13k  [0402]
R116  4.53k  [0402]
R121  0  [1206]
R122  0  [1206]
R221  102k  [0402]
R222  162k  [0402]
R226  499k  [0402]
R227  348k  [0402]
R228  162k  [0402]
R252  10k  [0402]
R254  1.27K  [0402]
R255  100k  [0402]
R256  10K  [0402]
R258  100k  [0402]
R284  0  [1206]
R286  0  [0402]
R296  0  [1206]
R297  0  [1206]
R298  40.2k  [0402]
R299  0  [0805]
R300  0  [0805]
R301  0  [0805]
R302  0  [0805]
R303  0  [0805]
R304  0  [0805]
R305  0  [0805]
R316  0  [0805]
R317  0  [0402]
R318  0  [0402]
R319  0  [0402]
R320  0  [0402]
R321  0  [0402]
R330  205k  [0402]
SHN18  SHUNT HEADER
TP14  BLK  [TP_THVT_060_RND]
U12  TPS74401/QFN20  [qfn_20_197x197_0p65_rgw]
U31  TPS62095  [QFN_16_124x124_RGT]
U35  TPS62085  [QFN_RLT_7]
U37  TPS7A8500  [QFN20_RGR_p5mm]

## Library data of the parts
C1 C385 C427 C440 C441 C447 = CAP_NP_1: Mfr_Name: MURATA; Mfr_Part_Number: GRM155R71H103KA88D; TOL: 10%; VOLTAGE: 50V
C2 C3 = CAPACITOR_NP_1: Mfr_Name: MURATA; Mfr_Part_Number: GRM033R61A104KE15D; Note: DNI; TOL: 10%; Voltage: 10V
C5 C6 C8-C11 C13 C14 C16-C19 C21-C24 = CAP0402_0: Mfr_Name: MURATA; Mfr_Part_Number: GRM033R61A104KE15D; TOL: 10%; Voltage: 10V
C25 C333 C334 = CAP_NP_1: Mfr_Name: MURATA; Mfr_Part_Number: GRM033R71A103KA01D; TOL: 10%; VOLTAGE: 10V
C27 = CAP_0402_0.001uF_H
C28 = CAPACITOR_NP_1: Mfr_Name: MURATA; Mfr_Part_Number: GRM033R61A104KE15D; TOL: 10%; Voltage: 10V
C370 = CAP_NP_1: Mfr_Name: MURATA; Mfr_Part_Number: GRM155R71H103KA88D; Note: DNI; TOL: 10%; VOLTAGE: 50V
C107 C108 C111 C112 C115-C118 C122-C129 C132 C133 C136 C137 C140 C141 C144 C145 C148 C149 C152 C153 C156 C157 C160 C161 C164 C165 C167 C169-C171 C174-C177 C375 C407 C438 C439 C446 = CAP0402_0: Mfr_Name: TDK; Mfr_Part_Number: C0603X7S1A104K030BC; TOL: 10%; Voltage: 10V
C449 C450 = CAP0402_0: Mfr_Name: MURATA; Mfr_Part_Number: GRM033R61A104KE15D; Note: DNI; TOL: 10%; Voltage: 10V
J1 = TMP_122841: Mfr_Name: Johnson Components; Mfr_Part_Number: 142-0711-841; TI_Silktext: DACCLKP
J11 = HEADER_2x5_100: TI_SILKTEXT: EPAP
J22 = HEADER_2x3_100: Mfr_Name: FCI; Mfr_Part_Number: 57202-G52-03LF; Note: SHUNT 1-2, 3-4, 5-6; TI_SILKTEXT: DAC CONFIG
J23 = HEADER_2x4_100: Mfr_Name: FCI; Mfr_Part_Number: 57202-G52-04LF; Note: SHUNT 1-2, 3-4, 5-6, 7-8; TI_SILKTEXT: SPI
J26 = SMA-THVT_142-0701-201_REC: TI_Silktext: CLKTXP
J27 = TMP_122841: Mfr_Name: Johnson Components; Mfr_Part_Number: 142-0711-841; Note: DNI; TI_Silktext: DACCLKN
JP1 = Jumper_1x3_100_0: Mfr_Name: SAMTEC; Mfr_Part_Number: HMTSW-103-07-G-S-.230; Note: (SHUNT 2-3); TI_Silktext: SLEEP
JP2 = Jumper_1x3_100_0: Mfr_Name: SAMTEC; Mfr_Part_Number: HMTSW-103-07-G-S-.230; Note: (SHUNT 1-2); TI_Silktext: TXENABLE
R1 = RES0603: Mfr_Name: Panasonic; Mfr_Part_Number: ERJ-1GN0R00C; Wattage: 1/20W
R2 R3 = RES0603: Mfr_Name: Panasonic; Mfr_Part_Number: ERJ-1GEF2940C; Note: DNI; TOL: 1%; Wattage: 1/20W
R4 R5 R243 = Res_0402_49.9: Mfr_Part_Number: ERJ-1GEF49R9C; Note: DNI
R9 R10 R289-R291 = Res_0402_10_H: Mfr_Part_Number: ERJ-2GE0R00X; Note: DNI
R11 = R_0: Mfr_Name: Panasonic; Mfr_Part_Number: ERJ-2RKF1001X; PART_NUMBER: Panasonic ERJ-2RKF1001X; TOL: 1%
R12 = Res_0402_1.8K: Mfr_Part_Number: ERJ-2RKF3651X
R103 R104 = R: Mfr_Name: PANASONIC; Mfr_Part_Number: ERJ-1GN0R00C; TOL: 5%
R210 R211 = RES0603: Mfr_Name: Panasonic; Mfr_Part_Number: ERJ-2RKF11R3X; TOL: 1%; Wattage: 1/10W
R212 = RES0603: Mfr_Name: Panasonic; Mfr_Part_Number: ERJ-2RKF71R5X; TOL: 1%; Wattage: 1/10W
R213-R215 = RES0603: Mfr_Name: Panasonic; Mfr_Part_Number: ERJ-2BSFR18X; TOL: 1%; Wattage: 1/16W
R239 R240 R244 R263-R266 R268 R269 R314 = R: Mfr_Name: PANASONIC; Mfr_Part_Number: ERJ-2GE0R00X; Note: DNI; TOL: 5%
R242 = Res_0402_49.9: Mfr_Part_Number: ERJ-2RKF49R9X; Note: DNI
R267 = Res_0402_Zero_H_DNI: Mfr_Part_Number: ERJ-1GEF1000C; Note: DNI
R29 R280 R287 = Res_0402_49.9: Mfr_Part_Number: ERJ-1GEF49R9C; Note: DNI; TOL: 1%; Wattage: 1/20W
R282 = Res_0402_49.9: Mfr_Part_Number: ERJ-2RKF97R6X
R288 R323 R324 = Res_0402_10_H: Mfr_Part_Number: ERJ-2GE0R00X; Note: DNI; TOL: 5%
SHN1 SHN2 SHN17 SHN18 = SHUNT_HEADER
SHN5-SHN11 = SHUNT_HEADER: Mfr_Name: Sullins; Mfr_Part_Number: NPN02SXLN-RC
SW1 = SW_PUSHBUTTON: Mfr_Name: C&K Components; Mfr_Part_Number: PTS635SL43 LFS
T1 = BALUN_NCR2-113+
T8 = TFMR_6_TCM2-43X+: Impedance Ratio: 2:1
TP1 TP2 TP14 = TESTPOINT_BLK
TP9 = TESTPOINT_BLUE: Mfr_Part_Number: 5004; TI_SILKTEXT: ALARM
TP10 = TESTPOINT_BLUE: Mfr_Part_Number: 5004; TI_SILKTEXT: TESTMODE
C106 C110 C114 C119 C131 C135 C139 C143 C147 C151 C155 C159 C163 C168 C218 C220 C373 C376 = CAP0201_0: CLASS: DISCRETE; Mfr_Name: TDK CORP; Mfr_Part_Number: C1608X7S0J106M080AC; TOL: 20%; VOLTAGE: 6.3V
C120 = CAPACITOR_NP_1: Mfr_Name: AVX; Mfr_Part_Number: 02016D105MAT2A; TOL: 20%; Voltage: 6.3V
C342-C353 C356-C358 C374 C377 = CAPACITOR_NP_1: Mfr_Name: TDK; Mfr_Part_Number: CL05B105KQ5NQNC; TOL: 10%; Voltage: 6.3V
R30 R250 = Res_0603_Zero_DNI: Mfr_Part_Number: ERJ-3GEY0R00V
R299-R305 R315 R316 = Res_0402_Zero_H_DNI: Mfr_Name: KEYSTONE; Mfr_Part_Number: 5106
U1 = DAC38RF80_10x10
C179 C400 = CAPACITOR_NP_1: Mfr_Name: Samsung; Mfr_Part_Number: GRM155R71C104KA88D; TOL: 10%; Voltage: 16V
C327 C329 C397 C399 C413 = CAPACITOR_NP_1: Mfr_Name: Murata; Mfr_Part_Number: GRM155R71H562KA88D; TOL: 10%; Voltage: 50V
C328 C398 = CAPACITOR_NP_1: Mfr_Name: MURATA; Mfr_Part_Number: GRM1555C1HR30WA01D; TOL: .05pF; Voltage: 50V
C330-C332 C401 C403 C404 = CAPACITOR_NP_1: Mfr_Name: Samsung; Mfr_Part_Number: CL05B102KO5NNNC; TOL: 10%; Voltage: 16V
C53 C59 C61 C247 C260 C364 C402 C433 = CAPACITOR_NP_1: Mfr_Name: MURATA; Mfr_Part_Number: GRM155R71C104KA88D; TOL: 10%; Voltage: 16V
J2 = TMP_122841: Mfr_Name: Johnson Components; Mfr_Part_Number: 142-0711-841; TI_Silktext: IOUTB/SE
J6 = TMP_122841: Mfr_Name: Johnson Components; Mfr_Part_Number: 142-0711-841; Note: <Note>; TI_Silktext: IOUTA
J7 = TMP_122841: Mfr_Name: Johnson Components; Mfr_Part_Number: 142-0711-841; TI_Silktext: IOUTA/SE
L1 L2 L7 L8 = CHOKE: Mfr_Name: Coilcraft; Mfr_Part_Number: 0402AF-561XJLU; Note: DNI
L9 L10 = CHOKE: Mfr_Name: Coilcraft; Mfr_Part_Number: 0402AF-561XJLU
R199 R229 = Res_0402_100_H: Mfr_Part_Number: ERJ-2GE0R00X; Note: DNI
R238 R241 R248 R249 = R: Mfr_Name: PANASONIC; Mfr_Part_Number: ERJ-3GEY0R00V; Note: DNI; TOL: 5%
R272-R274 = Res_0402_10_H: Mfr_Part_Number: ERJ-2GE0R00X; Note: <Note>
T5 T7 = TFMR_6_TCM3-452X+: Impedance Ratio: 2:1
C29 C32 C42 C43 C46-C48 C360 C365 C443 C448 = CAPACITOR_NP_1: Mfr_Name: MURATA; Mfr_Part_Number: GRM033R61A104KE15D; TOL: 10%; Voltage: 16V
C30 = CAP_NP_0: Mfr_Name: TDK; Mfr_Part_Number: C1005X7S0J684K050BC; TOL: 10%; VOLTAGE: 6.3V
C31 C50 = CAP_NP_0: Mfr_Name: MURATA; Mfr_Part_Number: GRM033R61A104KE15D; TOL: 10%; VOLTAGE: 16V
C33 = CAP_NP_0: Mfr_Name: AVX; Mfr_Part_Number: 0201ZD392KAT2A; TOL: 10%; VOLTAGE: 10V
C34 = CAP_NP_0: Mfr_Name: MURATA; Mfr_Part_Number: GRM0335C1E470JA01D; TOL: 5%; VOLTAGE: 25V
C35 C36 = CAP_0402_0.01uF_H: Mfr_Name: TDK; Mfr_Part_Number: C0603X7S1A104K030BC; TOL: 10%; VOLTAGE: 10V
C37 = CAP_0402_0.1uF: Mfr_Name: MURATA; Mfr_Part_Number: GRM033R61A104KE15D; Note: DNI; TOL: 10%; VOLTAGE: 16V
C38 C49 = CAP_0402_0.1uF_H: Mfr_Part_Number: GRM033R61A104KE15D; TOL: 10%; Voltage: 16V
C39 = CAP_0603_100pF_H: Mfr_Name: TDK; Mfr_Part_Number: C1005C0G1H101J050BA
C40 = CAP_0402_2200pF_H: Mfr_Name: Murata; Mfr_Part_Number: GRM155R71H222JA01J
C41 = CAP_0402_10pF_H: Mfr_Part_Number: GRM1555C1H100FA01D
C44 = CAP_0402_0.1uF_H: Mfr_Part_Number: GRM033R61A104KE15D; Note: DNI; TOL: 10%; Voltage: 16V
C45 = CAP_NP_0: Mfr_Name: MURATA; Mfr_Part_Number: GRM033R61A104KE15D; Note: DNI; TOL: 10%; VOLTAGE: 16V
C51 = CAPACITOR_NP_1: Mfr_Name: Kemet; Mfr_Part_Number: CBR02C120F3GAC; TOL: 1%; Voltage: 25V
C366 = CAPACITOR_NP_1: Mfr_Name: MURATA; Mfr_Part_Number: GRM033R61A104KE15D; Note: DNI; TOL: 10%; Voltage: 16V
C371 C372 C378-C383 = CAP_0402_0.01uF_H: Mfr_Part_Number: GRM033R71A103KA01D; TOL: 10%; VOLTAGE: 10V
FB1 = FERRITE_BEAD_0402_H: Isat: 500mA; Mfr_Name: MURATA; Mfr_Part_Number: BLM31PG121SN1L
J4 = SMA-THVT_142-0701-201_REC: TI_Silktext: LMK_CLKIN
J24 = SMA-THVT_142-0701-201_REC: TI_Silktext: DCLKOUT4P
J25 = SMA-THVT_142-0701-201_REC: TI_Silktext: OSCIN
JP3 JP10 = HDR_2x1_100: Note: SHUNT 1-2
R20 = Res_0402_24.9: Mfr_Part_Number: ERJ-1GEF2492C; Note: DNI
R21 = R_1: CLASS: DISCRETE; Mfr_Name: PANASONIC; Mfr_Part_Number: ERJ-1GEF3902C; TOL: 1%
R22 R23 R31 R36 R55 R57 = Res_0402_Zero_H_DNI: Mfr_Part_Number: ERJ-1GN0R00C
R24-R27 R41 R42 R45 R46 R50 R51 R56 R58 = Res_0402_249: Mfr_Part_Number: ERJ-1GEF2400C; Note: DNI
R28 = R_1: CLASS: DISCRETE; Mfr_Name: PANASONIC; Mfr_Part_Number: ERJ-1GEF6200C; TOL: 1%
R32 = Res_0402_18: Mfr_Part_Number: ERJ-2RKF18R0X
R33 R34 = Res_0402_270: Mfr_Part_Number: ERJ-2RKF2940X
R35 = Res_0402_49.9: Mfr_Part_Number: ERJ-2RKF49R9X
R37 R38 = Res_0402_249: Mfr_Part_Number: ERJ-1GEF2400C
R39 R40 = Res_0402_Zero_H_DNI: Mfr_Part_Number: ERJ-1GEF1000C
R43 R49 = RESISTOR_0: CLASS: DISCRETE; Mfr_Name: Panasonic; Mfr_Part_Number: ERJ-1GEF1300C; Note: DNI; TOL: 1%; Wattage: 1/20W
R44 = Res_0402_100_H: Mfr_Part_Number: ERJ-1GEF1000C; Note: DNI
R47 R53 = RESISTOR_0: CLASS: DISCRETE; Mfr_Name: Panasonic; Mfr_Part_Number: ERJ-1GEF82R0C; Note: DNI; TOL: 1%; Wattage: 1/20W
R48 = RESISTOR_0: CLASS: DISCRETE; Mfr_Name: PANASONIC; Mfr_Part_Number: ERJ-1GEF49R9C; Note: DNI; TOL: 1%; Wattage: 1/20W
R52 = Res_0402_100_H: Mfr_Part_Number: ERJ-1GEF1000C
R54 R218 R219 = RESISTOR_0: CLASS: DISCRETE; Mfr_Name: PANASONIC; Mfr_Part_Number: ERJ-1GEF49R9C; TOL: 1%; Wattage: 1/20W
R106 R107 = Res_0603_100: Mfr_Part_Number: ERJ-1GEF1000C
R283 R329 = Res_0402_49.9: Mfr_Part_Number: ERJ-1GEF49R9C; TOL: 1%; Wattage: 1/20W
SJP1 = SMD_JUMPER_1x3: Mfr_Name: DNI; Mfr_Part_Number: DNI; Note: DNI; TI_SILK: SHUNT 1-2; TI_Silktext: EN
T3 = TFMR_5_TC1-1-13M+
U2 = LMK04828: Mfr_Name: Texas Instruments; Mfr_Part_Number: LMK04828BISQ/NOPB
U30 = NB7V33M: Mfr_Name: On Semi; Mfr_Part_Number: NB7V33MMNG
Y1 = OSC_SM_6_TCO-2100-SERIES_2: Mfr_Name: Crystek; Mfr_Part_Number: CVHD-950-122.880
C52 C58 = CAPACITOR_NP_1: Mfr_Name: MURATA; Mfr_Part_Number: GRM155R61A105KE15D; TOL: 10%; Voltage: 16V
C54 C60 = CAPACITOR_NP_1: Mfr_Name: MURATA; Mfr_Part_Number: GRM155R71H103KA88D; TOL: 10%; Voltage: 50V
C55-C57 C63 C64 = CAPACITOR_NP_1: Mfr_Name: TDK; Mfr_Part_Number: C1608X7R1E105K080AB; TOL: 10%; Voltage: 25V
C62 = CAP_NP_2: CLASS: DISCRETE; Mfr_Name: TDK; Mfr_Part_Number: C1608X5R1A106K080AC; TOL: 10%; VOLTAGE: 10V
D1 = LED: Mfr_Name: LITE ON; Mfr_Part_Number: LTST-C150KGKT; TI_Silktext: STAT 0
D2 = LED: Mfr_Name: LITE ON; Mfr_Part_Number: LTST-C150KGKT; TI_Silktext: STAT 1
D3 = LED: Mfr_Name: LITE ON; Mfr_Part_Number: LTST-C150KGKT; TI_Silktext: LMK LOCKED
D4 = LED: Mfr_Name: LITE ON; Mfr_Part_Number: LTST-C150KGKT; TI_Silktext: PLL2 LOCKED
FB2-FB11 = FERRITE_BEAD_0402_H: Isat: 500mA; Mfr_Name: MURATA; Mfr_Part_Number: BLM18AG121SN1D
J8 = SMA-THVT_142-0701-201_REC: TI_Silktext: LMK_SYNC
R59-R62 = RESISTOR_0: CLASS: DISCRETE; Mfr_Name: DALE; Mfr_Part_Number: CRCW0603750RFKEA
R148 = R: Mfr_Name: PANASONIC; Mfr_Part_Number: ERJ-2GE0R00X; TOL: 5%
R187 = RESISTOR_0: CLASS: DISCRETE; Mfr_Name: Panasonic; Mfr_Part_Number: ERJ-2RKF1301X
D8 = LED: CLASS: DISCRETE; Mfr_Name: LITE ON; Mfr_Part_Number: LTST-C171TBKT; TI_SILKTEXT: JESD_SYNC
D9 = LED: CLASS: DISCRETE; Mfr_Name: LITE ON; Mfr_Part_Number: LTST-C171TBKT; TI_SILKTEXT: SPARE_LED1
D10 = LED: CLASS: DISCRETE; Mfr_Name: LITE ON; Mfr_Part_Number: LTST-C171TBKT; TI_SILKTEXT: SPARE_LED2
J20 = CON_SMVT_40X10_ASP-134487-01: Mfr_Part_Number: SEAM-40-02.0-S-10-2-A-K-TR
Q1-Q3 = MMBT2222A: Mfr_Name: ON Semiconductor
R79 R81 R84 = R: Mfr_Name: PANASONIC; Mfr_Part_Number: ERJ-2RKF1001X; TOL: 1%; VOLTAGE: 1/10W
R80 R82 R83 = Res_0603_Zero_H: Mfr_Part_Number: ERJ-2GE0R00X
R232 = Res_0603_Zero_H: Mfr_Part_Number: ERJ-2GE0R00X; Note: DNI
C236 C241 C250 C254 C258 C262 C268 C271 C274 C387 C415 C420 C445 = CAP_NP_1: Mfr_Name: SAMSUNG; Mfr_Part_Number: CL21B106KOQNNNE; TOL: 10%; VOLTAGE: 16V
C237 C242 C251 C263 C269 C272 C275 C386 C419 C444 = CAP_NP_0: Mfr_Name: Samsung Electro-Mechanics America, Inc; Mfr_Part_Number: CL10B105KO8NNNC; TOL: 10%; VOLTAGE: 16V
C248 C259 C435 = CAP_NP_0: Mfr_Name: TDK; Mfr_Part_Number: C1608X7R1E105K080AE; TOL: 10%; VOLTAGE: 25V
C249 = CAP_NP_1: Mfr_Name: TDK; Mfr_Part_Number: C4532X7R1C336M250KC; Note: DNI; TOL: 20%; VOLTAGE: 16V
C253 = CAP_1210_22uF: Mfr_Name: MURATA; Mfr_Part_Number: GRM31CR71A226KE15L; Note: DNI
C384 C428 C429 = CAP_NP_1: Mfr_Name: MURATA; Mfr_Part_Number: GRM31CR71A226KE15L; TOL: 10%; VOLTAGE: 10V
C394 = CAP_NP_1: Mfr_Name: MURATA; Mfr_Part_Number: GRM21BR61E106KA73L; TOL: 10%; VOLTAGE: 25V
C395 = CAP: Mfr_Name: Murata; Mfr_Part_Number: GRM31CR71A226KE15L; TOL: 10%; VOLTAGE: 10V
C432 = CAPACITOR_NP_1: Mfr_Name: TDK; Mfr_Part_Number: C1608X7R1E105K080AE; TOL: 10%; Voltage: 25V
C434 = CAP_NP_0: Mfr_Name: TDK; Mfr_Part_Number: C2012X5R1A476M125AC; TOL: 10%; VOLTAGE: 10V
C436 = CAP_NP_1: Mfr_Name: TDK; Mfr_Part_Number: C2012X5R1A476M125AC; TOL: 10%; VOLTAGE: 10V
FB19 FB22 FB24 FB26-FB28 FB37 FB40 FB42 = BEAD_NFM31P: Mfr_Name: Murata; Mfr_Part_Number: NFM31PC276B0J3L; Tolerance: 20%
FB20 = BEAD_NFM31P: Mfr_Name: Murata; Mfr_Part_Number: NFM31PC276B0J3; Tolerance: 20%
JP8 = JUMPER_1x2_0: TI_Silktext: <TI_Silktext>
L3 = CHOKE: Mfr_Name: Coilcraft; Mfr_Part_Number: XFL4020-102MEC
L5 = CHOKE: Mfr_Name: Coilcraft; Mfr_Part_Number: XFL4015-471MEB
PP1 = PROBE_POINT_0: TI_Silktext: +0.9V_VDDL1
PP2 = PROBE_POINT_0: TI_Silktext: +0.9V_VDDL2
PP3 = PROBE_POINT_0: TI_Silktext: +0.9V_VDDCLK
PP4 = PROBE_POINT_0: TI_Silktext: +0.9V_VDDA
PP5 PP24 PP27 = PROBE_POINT_0: TI_Silktext: +0.9V_VDDPLL
PP9 PP26 = PROBE_POINT_0: TI_Silktext: +0.9V_VDDT
PP10 = PROBE_POINT_0: TI_Silktext: +0.9V_VDD
R115 = R: Mfr_Name: Panasonic; Mfr_Part_Number: ERJ-2RKF1131X; TOL: 1%
R116 = R: Mfr_Name: Panasonic; Mfr_Part_Number: ERJ-2RKF4531X; TOL: 1%
R121 R122 R297 = Res_0402_Zero_H_DNI: Mfr_Name: KEYSTONE; Mfr_Part_Number: 5108
R221 = Res_0603_Zero_H: Mfr_Part_Number: ERJ-2RKF1023X; Note: DNI
R222 R228 = R: Mfr_Name: Panasonic; Mfr_Part_Number: ERJ-2RKF1623X; TOL: 1%
R226 = Res_0603_Zero_H: Mfr_Part_Number: ERJ-2RKF4993X
R227 = Res_0603_Zero_H: Mfr_Part_Number: ERJ-2RKF3483X; Note: DNI
R252 = R_0: CLASS: DISCRETE; Mfr_Name: PANASONIC; Mfr_Part_Number: ERJ-2RKF1002X; TOL: 1%
R254 = R_0: Mfr_Name: PANASONIC; Mfr_Part_Number: ERJ-2RKF1271X; Note: DNI; TOL: 1%
R255 = R: Mfr_Name: Panasonic; Mfr_Part_Number: ERJ-2RKF1003X; TOL: 1%
R256 = RESISTOR: 10K ohm, +/-1%, 1/16W(0402); Mfr_Name: PANASONIC; Mfr_Part_Number: ERJ-2RKF1002X; Note: DNI; Package: SMD; TOL: 1%; Terasic_Prt: M0597; Type: Resistor
R258 = R_1: CLASS: DISCRETE; Mfr_Name: PANASONIC; Mfr_Part_Number: ERJ-2RKF1003X; TOL: 1%; VOLTAGE: 1/10W
R284 R296 = Res_0402_Zero_H_DNI: Mfr_Name: KEYSTONE; Mfr_Part_Number: 5108; Note: DNI
R286 R317 = R: Mfr_Name: Panasonic; Mfr_Part_Number: ERJ-2GE0R00X; TOL: 5%
R298 = Res_0603_Zero_H: Mfr_Part_Number: ERJ-2RKF4022X
R318 R319 = R: Mfr_Name: Panasonic; Mfr_Part_Number: ERJ-2GE0R00X; Note: DNI; TOL: 5%
R320 = Res_0402_Zero_H_DNI: Mfr_Name: Panasonic; Mfr_Part_Number: ERJ-2GE0R00X; TOL: 5%
R321 = Res_0402_Zero_H_DNI: Mfr_Name: Panasonic; Mfr_Part_Number: ERJ-2GE0R00X; Note: DNI; TOL: 5%
R330 = Res_0603_Zero_H: Mfr_Part_Number: ERJ-2RKF2053X
U12 = TPS74401_QFN20: Mfr_Name: Texas Instruments; Mfr_Part_Number: TPS74401RGWT
U31 = TPS62095: Mfr_Name: Texas Instruments; Mfr_Part_Number: TPS62095RGTR
U35 = TPS62085_62086_62087: Mfr_Name: Texas Instruments; Mfr_Part_Number: TPS62085RLTR
U37 = TPS7A8500

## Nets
1.8VCLK: C379.1 C380.1 C381.1 C382.1 C383.1 C419.1 JP10.1 PP26.1 R218.1 R219.1 U30.9(VCC) U30.12(VCC) U30.13(VCC) U30.14(VCC) U30.16(VCC)
+0.9V_VDDA: C139.1 C140.1 C141.1 C271.1 C272.1 C348.2 FB27.3 PP4.1 U1.F11(VDDA_09V) U1.J11(VDDA_09V)
+0.9V_VDDCLK: C135.1 C136.1 C137.1 C268.1 C269.1 C343.2 FB26.3 PP3.1 R320.1 U1.G9(VDDCLK_09V) U1.H9(VDDCLK_09V)
+0.9V_VDDL1: C110.1 C111.1 C112.1 C250.1 C251.1 C345.2 FB22.3 PP1.1 U1.G8(VDDL1_09V) U1.H8(VDDL1_09V)
+0.9V_VDDL2: C131.1 C132.1 C133.1 C262.1 C263.1 C347.2 FB24.3 PP2.1 U1.G10(VDDL2_09V) U1.H10(VDDL2_09V)
+0.9V_VDDPLL: C143.1 C144.1 C145.1 C274.1 C275.1 C344.2 FB28.3 PP5.1 U1.D8(VDDPLL_09V) U1.E8(VDDPLL_09V)
+0.9V_VDDT: C106.1 C107.1 C108.1 C241.1 C242.1 C342.2 FB20.3 PP9.1 U1.H3(VDDT_09V) U1.J3(VDDT_09V)
+0.9V_VDDTX: C375.1 C376.1 C377.2 C386.1 C387.1 FB37.3 PP24.1 U1.B6(VDDTX)
+1.2V: R255.1
+1.8V_VDDA: C147.1 C148.1 C149.1 C349.2 U1.G11(VDDA18) U1.H11(VDDA18) ; also on sheet 9
+1.8V_VDDAPLL: C159.1 C160.1 C161.1 C351.2 U1.B9(VDDAPLL18) U1.B10(VDDAPLL18) ; also on sheet 9
+1.8V_VDDIO: C168.1 C169.1 C353.2 JP1.1(Pin1) JP2.1(Pin1) R11.1 U1.H5(VDDIO18) ; also on sheet 9
+1.8V_VDDOUTA: C179.1 C364.2 C400.1 C402.2 L1.2 L2.1 L7.2 L8.1 L9.1 L10.1 R250.1 ; also on sheet 9
+1.8V_VDDR: C174.1 C175.1 C220.1 C356.2 U1.H2(VDDR18) U1.J2(VDDR18) ; also on sheet 9
+1.8V_VDDS: C167.1 C171.1 C218.1 C358.2 U1.B3(VDDS18) U1.B4(VDDS18) ; also on sheet 9
+1.8V_VDDTX: C170.1 C373.1 C374.2 U1.B7(VDDTX18) ; also on sheet 9
+1.8V_VDDVCO: C155.1 C156.1 C157.1 C352.2 U1.D9(VDDAVCO18) U1.E9(VDDAVCO18) ; also on sheet 9
+3.3VCLK: FB1.2 FB2.1 FB3.1 FB4.1 FB5.1 FB6.1 FB10.1 FB11.1 R20.1 R43.1 R49.1 SJP1.3(Pin3) ; also on sheet 9
+5VIN: C384.1 C394.1 C415.1 C432.2 D8.1(ANODE) D9.1(ANODE) D10.1(ANODE) U12.10(BIAS) U31.3(DEF) U31.10(AVIN) U31.11(PVIN2) U31.12(PVIN1) U31.13(EN) U35.1(EN) U35.7(IN) U37.12(BIAS) ; also on sheet 9 10
-1.8V_VEE: C163.1 C164.1 C165.1 C176.1 C177.1 C357.2 U1.D10(VEE_-1.8V) U1.E10(VEE_-1.8V) U1.K10(VEE_-1.8V) U1.L10(VEE_-1.8V) ; also on sheet 9
GND: C27.2 C28.2 C31.2 C34.2 C37.1 C38.1 C39.1 C40.1 C41.1 C46.1 C51.1 C52.1 C53.1 C54.1 C55.1 C56.1 C57.1 C58.1 C59.1 C60.1 C61.2 C62.2 C63.1 C64.1 C106.2 C107.2 C108.2 C110.2 C111.2 C112.2 C114.2 C115.2 C116.2 C117.2 C118.2 C119.2 C120.1 C122.2 C123.2 C124.2 C125.2 C126.2 C127.2 C128.2 C129.2 C131.2 C132.2 C133.2 C135.2 C136.2 C137.2 C139.2 C140.2 C141.2 C143.2 C144.2 C145.2 C147.2 C148.2 C149.2 C151.2 C152.2 C153.2 C155.2 C156.2 C157.2 C159.2 C160.2 C161.2 C163.2 C164.2 C165.2 C167.2 C168.2 C169.2 C170.2 C171.2 C174.2 C175.2 C176.2 C177.2 C179.2 C218.2 C220.2 C236.2 C237.2 C241.2 C242.2 C247.1 C248.2 C249.2 C250.2 C251.2 C253.1 C254.2 C258.2 C259.2 C260.1 C262.2 C263.2 C268.2 C269.2 C271.2 C272.2 C274.2 C275.2 C327.2 C328.2 C331.1 C332.1 C342.1 C343.1 C344.1 C345.1 C346.1 C347.1 C348.1 C349.1 C350.1 C351.1 C352.1 C353.1 C356.1 C357.1 C358.1 C364.1 C373.2 C374.1 C375.2 C376.2 C377.1 C379.2 C380.2 C381.2 C382.2 C383.2 C384.2 C386.2 C387.2 C394.2 C395.2 C397.2 C398.2 C400.2 C402.1 C403.1 C404.1 C415.2 C419.2 C420.2 C427.1 C428.2 C429.2 C432.1 C433.1 C434.2 C435.2 C436.2 C440.1 C444.2 C445.2 C446.2 C447.1 D1.2(CATHODE) D2.2(CATHODE) D3.2(CATHODE) D4.2(CATHODE) FB19.2 FB20.2 FB22.2 FB24.2 FB26.2 FB27.2 FB28.2 FB37.2 FB40.2 FB42.2 J1.2(GND) J1.3(GND) J1.4(GND) J1.5(GND) J2.2(GND) J2.3(GND) J2.4(GND) J2.5(GND) J4.2(GND) J4.3(GND) J4.4(GND) J4.5(GND) J6.2(GND) J6.3(GND) J6.4(GND) J6.5(GND) J7.2(GND) J7.3(GND) J7.4(GND) J7.5(GND) J8.2(GND) J8.3(GND) J8.4(GND) J8.5(GND) J11.2 J11.4 J11.6 J11.8 J11.10 J20.A1 J20.A4 J20.A5 J20.A8 J20.A9 J20.A12 J20.A13 J20.A16 J20.A17 J20.A20 J20.A21 J20.A24 J20.A25 J20.A28 J20.A29 J20.A32 J20.A33 J20.A36 J20.A37 J20.A40 J20.B2 J20.B3 J20.B6 J20.B7 J20.B10 J20.B11 J20.B14 J20.B15 J20.B18 J20.B19 J20.B22 J20.B23 J20.B26 J20.B27 J20.B30 J20.B31 J20.B34 J20.B35 J20.B38 J20.B39 J20.C1 J20.C4 J20.C5 J20.C8 J20.C9 J20.C12 J20.C13 J20.C16 J20.C17 J20.C20 J20.C21 J20.C24 J20.C25 J20.C28 J20.C29 J20.C32 J20.C33 J20.C36 J20.C38 J20.C40 J20.D2 J20.D3 J20.D6 J20.D7 J20.D10 J20.D13 J20.D16 J20.D19 J20.D22 J20.D25 J20.D28 J20.D37 J20.D39 J20.E1 J20.E4 J20.E5 J20.E8 J20.E11 J20.E14 J20.E17 J20.E20 J20.E23 J20.E26 J20.E29 J20.E32 J20.E35 J20.E38 J20.E40 J20.F3 J20.F6 J20.F9 J20.F12 J20.F15 J20.F18 J20.F21 J20.F24 J20.F27 J20.F30 J20.F33 J20.F36 J20.F39 J20.G1 J20.G4 J20.G5 J20.G8 J20.G11 J20.G14 J20.G17 J20.G20 J20.G23 J20.G26 J20.G29 J20.G32 J20.G35 J20.G38 J20.G40 J20.H3 J20.H6 J20.H9 J20.H12 J20.H15 J20.H18 J20.H21 J20.H24 J20.H27 J20.H30 J20.H33 J20.H36 J20.H39 J20.J1 J20.J4 J20.J5 J20.J8 J20.J11 J20.J14 J20.J17 J20.J20 J20.J23 J20.J26 J20.J29 J20.J32 J20.J35 J20.J38 J20.J40 J20.K2 J20.K3 J20.K6 J20.K9 J20.K12 J20.K15 J20.K18 J20.K21 J20.K24 J20.K27 J20.K30 J20.K33 J20.K36 J20.K39 J24.2(GND) J24.3(GND) J24.4(GND) J24.5(GND) J25.2(GND) J25.3(GND) J25.4(GND) J25.5(GND) J26.2(GND) J26.3(GND) J26.4(GND) J26.5(GND) J27.2(GND) J27.3(GND) J27.4(GND) J27.5(GND) JP1.3(Pin3) JP2.3(Pin3) JP8.1 Q1.2(E) Q2.2(E) Q3.2(E) R2.2 R3.2 R4.2 R5.2 R12.2 R21.2 R24.2 R25.2 R26.2 R27.2 R28.2 R29.2 R33.2 R34.2 R37.2 R38.2 R41.2 R42.2 R45.2 R46.2 R47.2 R48.2 R50.2 R51.2 R53.2 R54.2 R56.2 R58.2 R106.2 R107.2 R116.2 R187.1 R222.2 R228.2 R239.2 R240.2 R242.2 R243.2 R256.2 R263.2 R264.2 R265.2 R266.2 R268.2 R269.2 R280.1 R282.2 R283.2 R287.2 R317.1 R318.1 R319.1 R329.2 SJP1.1(Pin1) SW1.1 T1.1(GND1) T1.3(GND2) T1.5(GND3) T3.2(secondary_ct) T3.4(primary) T8.1(primary1_GND) T8.2(primary2_GND) TP1.1(TP) TP2.1(TP) TP14.1(TP) U1.A2(DGND) U1.A8(VSSCLK) U1.A11(VSSCLK) U1.B2(DGND) U1.B8(VSSCLK) U1.B11(VSSCLK) U1.B12(VSSCLK) U1.C2(DGND) U1.C11(AGND) U1.C12(AGND) U1.D2(DGND) U1.D6(DGND) U1.D11(AGND) U1.E2(DGND) U1.E7(DGND) U1.E11(AGND) U1.F2(DGND) U1.F6(DGND) U1.F8(VSSCLK) U1.F9(VSSCLK) U1.F10(VSSCLK) U1.F12(AGND) U1.G2(DGND) U1.G7(DGND) U1.H6(DGND) U1.J7(DGND) U1.J8(VSSCLK) U1.J9(VSSCLK) U1.J10(VSSCLK) U1.J12(AGND) U1.K2(DGND) U1.K11(AGND) U1.L2(DGND) U1.L3(DGND) U1.L4(DGND) U1.L5(DGND) U1.L11(AGND) U1.M6(DGND) U1.M11(AGND) U1.M12(AGND) U2.65(DAP) U12.12(GND) U12.21(PWRPAD) U30.6(GND) U30.7(GND) U30.8(GND) U30.17(PWRPAD) U31.6(AGND) U31.14(PGND) U31.15(PGND) U31.17(PWRPAD) U35.5(GND) U37.8(GND) U37.18(GND) U37.21(THERMPAD) Y1.3(GND) ; also on sheet 9 10
VDD: C114.1 C115.1 C116.1 C117.1 C118.1 C122.1 C123.1 C124.1 C126.1 C127.1 C128.1 C129.1 C236.1 C237.1 C346.2 FB19.3 PP10.1 R254.1 R286.1 R298.2 R314.2 U1.A5(VDDDIG_09V) U1.B5(VDDDIG_09V) U1.C5(VDDDIG_09V) U1.D5(VDDDIG_09V) U1.D7(VDDDIG_09V) U1.E3(VDDDIG_09V) U1.E4(VDDDIG_09V) U1.E5(VDDDIG_09V) U1.E6(VDDDIG_09V) U1.F4(VDDDIG_09V) U1.F5(VDDDIG_09V) U1.G4(VDDDIG_09V) U1.G5(VDDDIG_09V)
VDDE: C119.1 C120.2 C125.1 C446.1 R314.1 R315.2 U1.F7(VDDDIG_09V) U1.G6(VDDDIG_09V) U1.H7(VDDDIG_09V) U1.J6(VDDDIG_09V)
VDDE_09: C444.1 C445.1 FB42.3 PP27.1 R315.1
VDDOUT18: C151.1 C152.1 C153.1 C350.2 R250.2 U1.G12(VDDOUT18) U1.H12(VDDOUT18)
ALARM: TP9.1(TP) U1.K8(ALARM)
AMUX0: J22.4 U1.G3(AMUX0)
AMUX1: J22.2 U1.F3(AMUX1)
ATEST: J22.5 U1.C8(ATEST)
CAR_SYSREF_M: R23.1 R24.1 U2.4(SDCLKOUT1n)
CAR_SYSREF_P: R22.1 R25.1 U2.3(SDCLKOUT1p)
CAR_SYSREFM: J20.G10 R23.2
CAR_SYSREFP: J20.G9 R22.2
CLK-IN: R30.1 R32.2 R34.1 T3.6(primary_dot)
CLK_LAO_0M: J20.G7 R57.2
CLK_LAO_0P: J20.G6 R55.2
CLKIN1_N: C36.2 C37.2 C371.2 U2.35(CLKIN1n/FBCLKINn/FINn)
CLKIN1_P: C35.2 C372.2 U2.34(CLKIN1p/FBCLKINp/FINp)
CLKINN: C36.1 R35.2 T3.3(secondary)
CLKINP: C35.1 R29.1 R30.2 R35.1 T3.1(secondary_dot)
CLKLA_0M: R57.1 R58.1 U2.63(DCLKOUT12n)
CLKLA_0P: R55.1 R56.1 U2.62(DCLKOUT12p)
CLKN: C3.1 R36.2
CLKP: C2.1 R31.2
CP1: C30.1 C31.1 R20.2 U2.32(CPOUT1) Y1.1(VC)
CP2: C33.1 C34.1 U2.46(CPOUT2)
DAC_RESET: C27.1 R11.2 SW1.2 U1.K9(RESETB) ; also on sheet 10
DAC_SCLK: J23.6 ; also on sheet 10
DAC_SDENB: J23.4 ; also on sheet 10
DAC_SDIO: J23.2 ; also on sheet 10
DAC_SDO: J23.8 ; also on sheet 10
DACCLK_IN: J1.1(CENTER) R215.2 R324.1
DACCLK_N: C3.2 C334.2 C449.2 U1.A9(DACCLKN)
DACCLK_P: C2.2 C333.2 C450.2 U1.A10(DACCLKP)
DACCLK_SE: C25.1 C370.2 R1.2 R2.1
DACCLKSE: R1.1 R3.1 U1.A12(DACCLKSE)
DCLKOUT4P: C365.1 U2.24(DCLKOUT4p)
DIV_IN: C378.1 R214.2 R243.1 R282.1
DP0_C2M_N_A: C24.1 J20.C3
DP0_C2M_P_A: C23.1 J20.C2
DP1_C2M_N_A: C21.1 J20.A23
DP1_C2M_P_A: C22.1 J20.A22
DP2_C2M_N_A: C18.1 J20.A27
DP2_C2M_P_A: C19.1 J20.A26
DP3_C2M_N_A: C17.1 J20.A31
DP3_C2M_P_A: C16.1 J20.A30
DP4_C2M_N_A: C13.1 J20.A35
DP4_C2M_P_A: C14.1 J20.A34
DP5_C2M_N_A: C10.1 J20.A39
DP5_C2M_P_A: C11.1 J20.A38
DP6_C2M_N_A: C8.1 J20.B37
DP6_C2M_P_A: C9.1 J20.B36
DP7_C2M_N_A: C5.1 J20.B33
DP7_C2M_P_A: C6.1 J20.B32
EXTIO: C28.1 U1.C10(EXTIO)
FMC_DAC_SCLK: J20.C14 R289.2
FMC_DAC_SDENB: J20.D15 R290.2
FMC_DAC_SDIO: J20.C15 R291.2
FMC_DAC_SDO: J20.D14 R288.2
FMC_LMK_CS: J20.H17 ; also on sheet 10
FMC_LMK_SCK: J20.G15 ; also on sheet 10
FMC_LMK_SDIO: J20.G16 ; also on sheet 10
FMC_LMK_SDO: J20.H16 ; also on sheet 10
FPGA_CLK1_N: C43.2 J20.K5
FPGA_CLK1_P: C42.2 J20.K4
FPGA_CLK1N: C43.1 R46.1 U2.52(DCLKOUT8n)
FPGA_CLK1P: C42.1 R45.1 U2.51(DCLKOUT8p)
FPGA_CLK2_N: C48.2 J20.J3
FPGA_CLK2_P: C47.2 J20.J2
FPGA_CLK2N: C48.1 R50.1 U2.50(SDCLKOUT9n)
FPGA_CLK2P: C47.1 R51.1 U2.49(SDCLKOUT9p)
FTDI_TCK: U1.K4(TCLK) ; also on sheet 10
FTDI_TDI: U1.H4(TDI) ; also on sheet 10
FTDI_TDO: U1.J4(TDO) ; also on sheet 10
FTDI_TMS: U1.K5(TMS) ; also on sheet 10
FTDI_TRSTB: U1.J5(TRSTB) ; also on sheet 10
GPIO0: J20.H28 R10.1
GPIO1: J20.H29 R9.1
GTX_CLKM: C32.2 J20.D5
GTX_CLKP: C29.2 J20.D4
GTXCLKM: C32.1 R26.1 U2.2(DCLKOUT0n)
GTXCLKP: C29.1 R27.1 U2.1(DCLKOUT0p)
IFORCE: J22.1 U1.D3(IFORCE)
IOUTA: J6.1(CENTER) R269.1 R273.1
IOUTA_SE: J7.1(CENTER) R264.1 R274.1
IOUTAM: L8.2 R229.1 R241.1 T7.6(secondary) U1.K12(VOUTAM)
IOUTAP: L7.1 R229.2 R239.1 R248.1 T7.4(secondary_dot) U1.L12(VOUTAP)
IOUTB: J2.1(CENTER) R266.1 R272.1
IOUTBM: L2.2 R199.1 R240.1 R249.2 T5.6(secondary) U1.D12(VOUTBP)
IOUTBP: L1.1 R199.2 R238.2 T5.4(secondary_dot) U1.E12(VOUTBM)
LMK LOCKED: D3.1(ANODE) R61.1
LMK_CLKIN: J4.1(CENTER) R32.1 R33.1
LMK_CS: U2.18(\\~{CS}) ; also on sheet 10
LMK_DACCLKSE: C25.2 C360.2 R287.1
LMK_SCK: U2.19(SCK) ; also on sheet 10
LMK_SDIO: U2.20(SDIO) ; also on sheet 10
LMK_SDO: R187.2 U2.5(RESET) ; also on sheet 10
NB7_RESET: R232.2 R244.1 U30.15(R) ; also on sheet 10
OSCINN: C50.2 C51.2 U2.44(OSCINn)
OSCINP: C45.2 C46.2 U2.43(OSCINp)
OSCN: C49.2 C50.1 C366.2 R49.2 R54.1
OSCP: C44.2 C45.1 R43.2 R48.1
PLL2 LOCKED: D4.1(ANODE) R62.1
RX0N: C24.2 U1.M4(RXN3)
RX0P: C23.2 U1.M5(RXP3)
RX1N: C21.2 U1.M3(RXN2)
RX1P: C22.2 U1.M2(RXP2)
RX2N: C18.2 U1.L1(RXN1)
RX2P: C19.2 U1.M1(RXP1)
RX3N: C17.2 U1.K1(RXN0)
RX3P: C16.2 U1.J1(RXP0)
RX4N: C13.2 U1.F1(RXN5)
RX4P: C14.2 U1.E1(RXP5)
RX5N: C10.2 U1.B1(RXN7)
RX5P: C11.2 U1.A1(RXP7)
RX6N: C8.2 U1.C1(RXN6)
RX6P: C9.2 U1.D1(RXP6)
RX7N: C5.2 U1.G1(RXN4)
RX7P: C6.2 U1.H1(RXP4)
SCLK: J23.5 R289.1 U1.L9(SCLK)
SDENB: J23.3 R290.1 U1.M8(SDENB)
SDIO: J23.1 R291.1 U1.M10(SDIO)
SDO: J23.7 R288.1 U1.M9(SDO)
SLEEP: JP1.2(Pin2) U1.L8(SLEEP)
SPARE1: J11.3 R10.2 U1.L7(GPO0)
SPARE2: J11.7 U1.L6(GPO1)
SPARE3: J11.1 R9.2 U1.K7(GPI0)
SPARE4: J11.5 U1.M7(GPI1)
STAT 0: D1.1(ANODE) R59.1
STAT 1: D2.1(ANODE) R60.1
SYNC: R148.2 U2.6(SYNC)
SYNC0BN: J20.F11 U1.C3(SYNC0BN)
SYNC0BP: J20.F10 U1.C4(SYNC0BP)
SYNC1BN: J20.F20 U1.C6(SYNC1BN)
SYNC1BP: J20.F19 U1.C7(SYNC1BP)
SYSREF+: R40.1 R41.1 U2.14(SDCLKOUT3n)
SYSREF-: R39.1 R42.1 U2.13(SDCLKOUT3p)
SYSREF-N: R5.1 R104.2 U1.A4(SYSREFN)
SYSREF-P: R4.1 R103.2 U1.A3(SYSREFP)
SYSREFN: R39.2 R104.1 R107.1
SYSREFP: R40.2 R103.1 R106.1
TESTMODE: TP10.1(TP) U1.K3(TESTMODE)
TXENABLE: JP2.2(Pin2) U1.K6(TXENABLE)
U37_BYPASS: R121.1 R122.2
VAR: C258.1 C259.1 C260.2 C395.1 FB40.1 L5.2 R227.1 R330.1 U12.5(IN1) U12.6(IN2) U12.7(IN3) U12.8(IN4) U12.11(EN) U35.4(VOS) ; also on sheet 9
VDIG: C428.1 C429.1 L3.2 R121.2 R221.1 R226.2 R296.1 U31.16(VOS)
VSENSE: J22.3 U1.D4(VSENSE)
Y2_N: R52.1 R53.1 Y1.4(OUT_N)
Y2_P: R44.1 R47.1 Y1.5(OUT_P)
YO2_N: C49.1 R52.2
YO2_P: C44.1 R44.2
N17488920: Q2.1(B) R82.2
N17488936: J20.C18 R80.1
N17488940: Q3.1(B) R83.2
N17488944: J20.D18 R83.1
N17488958: J20.D17 R82.1
N17488997: Q2.3(C) R81.2
N17489014: Q1.1(B) R80.2
N17489769: D9.2(CATHODE) R81.1
N17489787: D8.2(CATHODE) R79.1
N17489827: D10.2(CATHODE) R84.1
N17512943: R12.1 U1.C9(RBIAS)
N17771557: R297.1 R299.2 R300.2 R301.2 R302.2 R303.2 R304.2 R305.1 R316.2 R321.1
N17906763: J8.1(CENTER) R148.1
N17929635: C333.1 T1.6(SEC_DOT)
N17930246: C1.2 T1.2(PRI_DOT)
N17930866: C334.1 T1.4(SEC)
N17940319: C330.1 C332.2 L9.2 T5.5(secondary_ct)
N17940351: C327.1 C330.2 C331.2 T5.2(primary)
N17971041: C328.1 C329.1 R238.1 T5.3(primary_dot)
N18050278: C360.1 U2.40(OSCOUTp)
N18119227: C365.2 J24.1(CENTER)
N18119976: C366.1 J25.1(CENTER)
N18263954: C1.1 C370.1 R213.1 R242.1
N18264001: R210.2 R211.1 R212.1
N18264055: R212.2 R214.1
N18273767: R210.1 R213.2
N18273790: R211.2 R215.1
N18276385: C372.1 R218.2 U30.11(Q)
N18276388: C371.1 R219.2 U30.10(~{Q})
N18284547: C378.2 U30.2(CLK)
N18303715: FB37.1 R305.2
N18314120: C247.2 C248.1 C249.1 C253.2 C254.1 R252.1 R297.2 U12.1(OUT1) U12.18(OUT4) U12.19(OUT3) U12.20(OUT2)
N18315082: R227.2 R228.1 R330.2 U35.3(FB)
N18315084: L5.1 U35.6(SW)
N18332054: C397.1 C401.2 C403.2 T7.2(primary)
N18332084: C398.1 C399.1 R248.2 T7.3(primary_dot)
N18332340: C401.1 C404.2 L10.2 T7.5(secondary_ct)
N18332593: U30.1(VTCLK) U30.4(~{VTCLK}) U30.5(VREFAC)
N18332678: J20.H19 R232.1
N18336017: C438.1 R267.2 U1.A7(CLKTXP)
N18336019: C439.1 R267.1 U1.A6(CLKTXN)
N18340991: C407.2 J26.1(CENTER) R280.2
N18368981: C413.1 R241.2 T7.1(notused)
N18431978: C420.1 FB40.3 JP10.2
N18450019: J11.9 R244.2
N18458788: R249.1 T5.1(notused)
N18476239: JP3.1 Y1.6(VDD)
N18477216: R115.1 R116.1 U12.16(FB/SNS)
N18478341: R252.2 U12.9(PG)
N18509121: C385.2 U31.7(CP)
N18509124: C385.1 U31.8(CN)
N18509909: C427.2 U31.9(SS)
N18510430: R221.2 R222.1 R298.1 U31.5(FB)
N18510599: L3.1 U31.1(SW1) U31.2(SW2)
N18511967: R226.1 U31.4(PG)
N18517211: FB19.1 R122.1 R284.1
N18526029: C435.1 C436.1 R258.1 R296.2 U37.15(IN1) U37.16(IN2) U37.17(IN3)
N18526063: JP8.2 R258.2 U37.14(EN)
N18526106: C433.2 C434.1 C441.2 R284.2 U37.1(OUT1) U37.19(OUT2) U37.20(OUT3)
N18526174: C441.1 R254.2 R256.1 U37.3(FB)
N18526182: R255.2 U37.4(PG)
N18592420: C413.2 R263.1 R274.2
N18592542: C399.2 R268.1 R273.2
N18601933: C329.2 R265.1 R272.2
N18620813: C407.1 T8.3(primary_dot)
N18681043: C438.2 T8.4(secondary)
N18681093: C439.2 T8.6(secondary_dot)
N18682404: C443.1 U2.41(OSCOUTn)
N18687770: C440.2 U37.13(NR/SS)
N18712409: R286.2 U37.2(SNS)
N18715563: C443.2 R283.1
N18721299: FB22.1 R300.1
N18721339: FB24.1 R301.1
N18721381: FB26.1 R302.1
N18721425: FB27.1 R303.1
N18721471: FB28.1 R304.1
N18737961: FB42.1 R316.1
N18760111: R317.2 U37.7(200mV)
N18760140: R318.2 U37.6(100mV)
N18760186: R319.2 U37.5(50mV)
N18774590: FB20.1 R299.1
N18804219: C447.2 U12.15(SS)
N18805050: R115.2 R320.2 R321.2
N18850467: Q3.3(C) R84.2
N18850468: Q1.3(C) R79.2
N18851539: C30.2 R21.1
N18851540: C33.2 R28.1
N18858975: C450.1 R323.1
N18859137: J27.1(CENTER) R323.2
N18870035: C448.1 U2.25(DCLKOUT4n)
N18870037: C448.2 R329.1
N18893766: C449.1 R324.2
N19080738: C38.2 C39.2 C40.2 C41.2 FB1.1 JP3.2
N19081029: SJP1.2(Pin2) Y1.2(NC)
N19083254: R61.2 U2.31(STATUS_LD1)
N19083268: R62.2 U2.48(STATUS_LD2)
N19083286: R60.2 U2.59(CLKin_SEL1)
N19083328: R59.2 U2.58(CLKin_SEL0)
N19083344: C61.1 U2.12(LDObyp2)
N19083346: C62.1 U2.11(LDObyp1)
N19083364: C52.2 C53.2 C54.2 FB2.2 U2.10(VCC1_VCO) U2.33(VCC5_DIG) U2.36(VCC6_PLL1)
N19083444: FB7.2 U2.39(VCC7_OSCout)
N19083446: FB9.2 U2.45(VCC9_CP2)
N19083508: C58.2 C59.2 C60.2 FB6.2 FB7.1 FB8.1 FB9.1 U2.47(VCC10_PLL2)
N19083566: C56.2 FB3.2 U2.21(VCC3_SYSREF)
N19083568: C55.2 FB5.2 U2.17(VCC2_CG1)
N19083616: C64.2 FB11.2 U2.64(VCC12_CG0)
N19083618: C63.2 FB10.2 U2.53(VCC11_CG3)
N19083707: C57.2 FB4.2 U2.26(VCC4_CG2)
N19086842: R36.1 R38.1 U2.16(DCLKOUT2n)
N19086844: R31.1 R37.1 U2.15(DCLKOUT2p)
N19234861: FB8.2 U2.42(VCC8_OSCin)

Not connected (* = marked no-connect by the designer): J20 A2 A3 A6 A7 A10 A11 A14* A15* A18* A19* B1 B4 B5 B8 B9 B12 B13 B16 B17 B20 B21 B24 B25 B28 B29 B40 C6 C7 C10* C11* C19* C22* C23* C26* C27* C30* C31* C34 C35 C37 C39 D1 D8 D9 D11 D12 D20 D21 D23 D24 D26 D27 D29 D30 D31 D32 D33 D34 D35 D36 D38 D40 E2 E3 E6 E7 E9 E10 E12 E13 E15 E16 E18 E19 E21 E22 E24 E25 E27 E28 E30 E31 E33 E34 E36 E37 E39 F1 F2 F4 F5 F7 F8 F13 F14 F16 F17 F22 F23 F25 F26 F28 F29 F31 F32 F34 F35 F37 F38 F40 G2 G3 G12 G13 G18 G19 G21 G22 G24 G25 G27 G28 G30 G31 G33 G34 G36 G37 G39 H1 H2 H4 H5 H7 H8 H10 H11 H13 H14 H20 H22 H23 H25 H26 H31 H32 H34 H35 H37 H38 H40 J6 J7 J9 J10 J12 J13 J15 J16 J18 J19 J21 J22 J24 J25 J27 J28 J30 J31 J33 J34 J36 J37 J39 K1 K7 K8 K10 K11 K13 K14 K16 K17 K19 K20 K22 K23 K25 K26 K28 K29 K31 K32 K34 K35 K37 K38 K40; J22 6; T8 5(NC)*; U2 7(NC1) 8(NC2) 9(NC3) 22(SDCLKOUT5p) 23(SDCLKOUT5n) 27(DCLKOUT6p) 28(DCLKOUT6n) 29(SDCLKOUT7p) 30(SDCLKOUT7n) 37(CLKIN0p) 38(CLKIN0n) 54(DCLKOUT10p) 55(DCLKOUT10n) 56(SDCLKOUT11p) 57(SDCLKOUT11n) 60(SDCLKOUT13p) 61(SDCLKOUT13n); U12 2(NC) 3(NC1) 4(NC2) 13(NC3) 14(NC4) 17(NC5); U30 3(~{CLK}); U35 2(PG); U37 9(400mV) 10(800mV) 11(1.6V)

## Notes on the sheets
sheet 1
- NOTES:
- 1)  DNI = DO NOT INSTALL
- Shared pad
- Shared pad
- Shared pad
- Shared pad
- Shared pad
- NOTES:
  Schematic default is  DAC38RF83.
  Install R239 and R240 for DAC38RF80.
sheet 3
- NOTES:
  Schematic default is  DAC38RF83.
  For DAC38RF80:
  Install R238, R241
  DNI C179, C400, L9, L10, T5, T7, C330, C331, C332,
             C401, C403, C404, C328, C327, C399, R273,
             C398, C397, J6
sheet 4
- TSW JESD Interface
  reference clock w/
  LVDS levels
- Place near Vc pin of Y1
  R20 and C31 form voltage divider
  set the center frequency voltage for PLL2 reference
- MATCHED LENGTH
- Place close to LMK
- R30 TO SHARE PADS W/ T3
- Place close to LMK
- Shared Pad
- MATCHED LENGTH
- JESD SYSREF
- MATCHED LENGTH
- Place close to LMK
- Shared Pad
- Y1 CMOS version OUTPUT on PIN 4
- JESD CORECLOCK
sheet 5
- Make sure this line does not hold LMK high
  before LMK can be programmed for SDO
sheet 6
- DAC
- CLOCK INPUT
- DACCLK
- USB PORT
- DAC38RF8x
- LMK04828
- PAGE 7
- SYSREF
- PAGES 2,3,4
- PAGE 5,6
- JESD204B
- INTERFACE
- PAGE 8
- POWER SUPPLIES
- PAGE 9,10
- Drawn:
- L NGUYEN     02/2016
- Engineer:
- E DWOBENG   02/2016
sheet 7
- 12500 TI Boulevard. Dallas, Texas 75243
sheet 8
- NOTES:
  To bypass LDO U37:  Install R298, R121, R122
                                      DNI R221, R296, R284
  To use LDO U34 (U35 output = 2.5V):  DNI R330
                                                                Install R227
- 4A
- 3A
- 4A
- 3A
